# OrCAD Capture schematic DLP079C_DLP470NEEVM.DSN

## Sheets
1 PAGE-07 Revision History
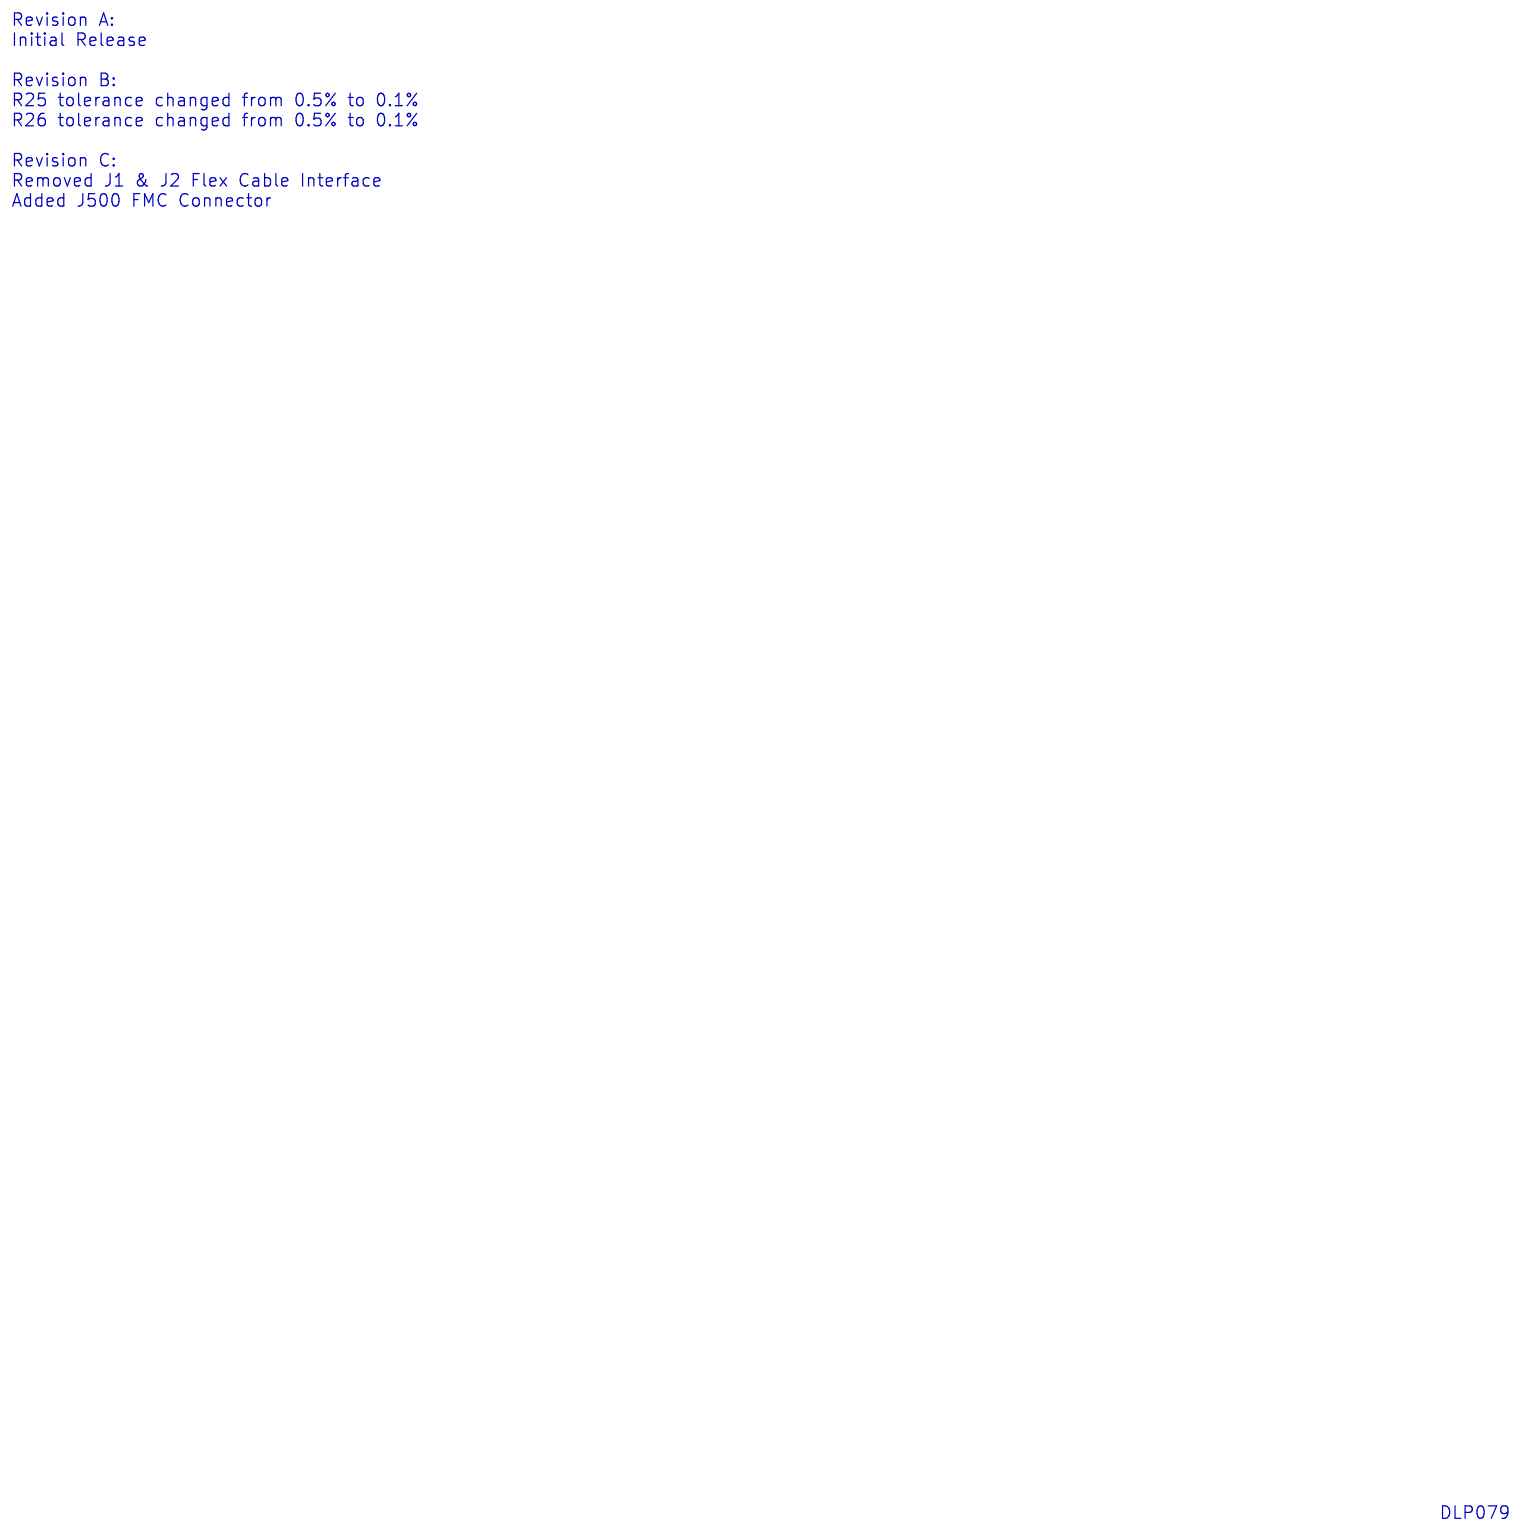
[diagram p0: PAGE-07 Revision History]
2 PAGE-03 Input FMC Connector: size D
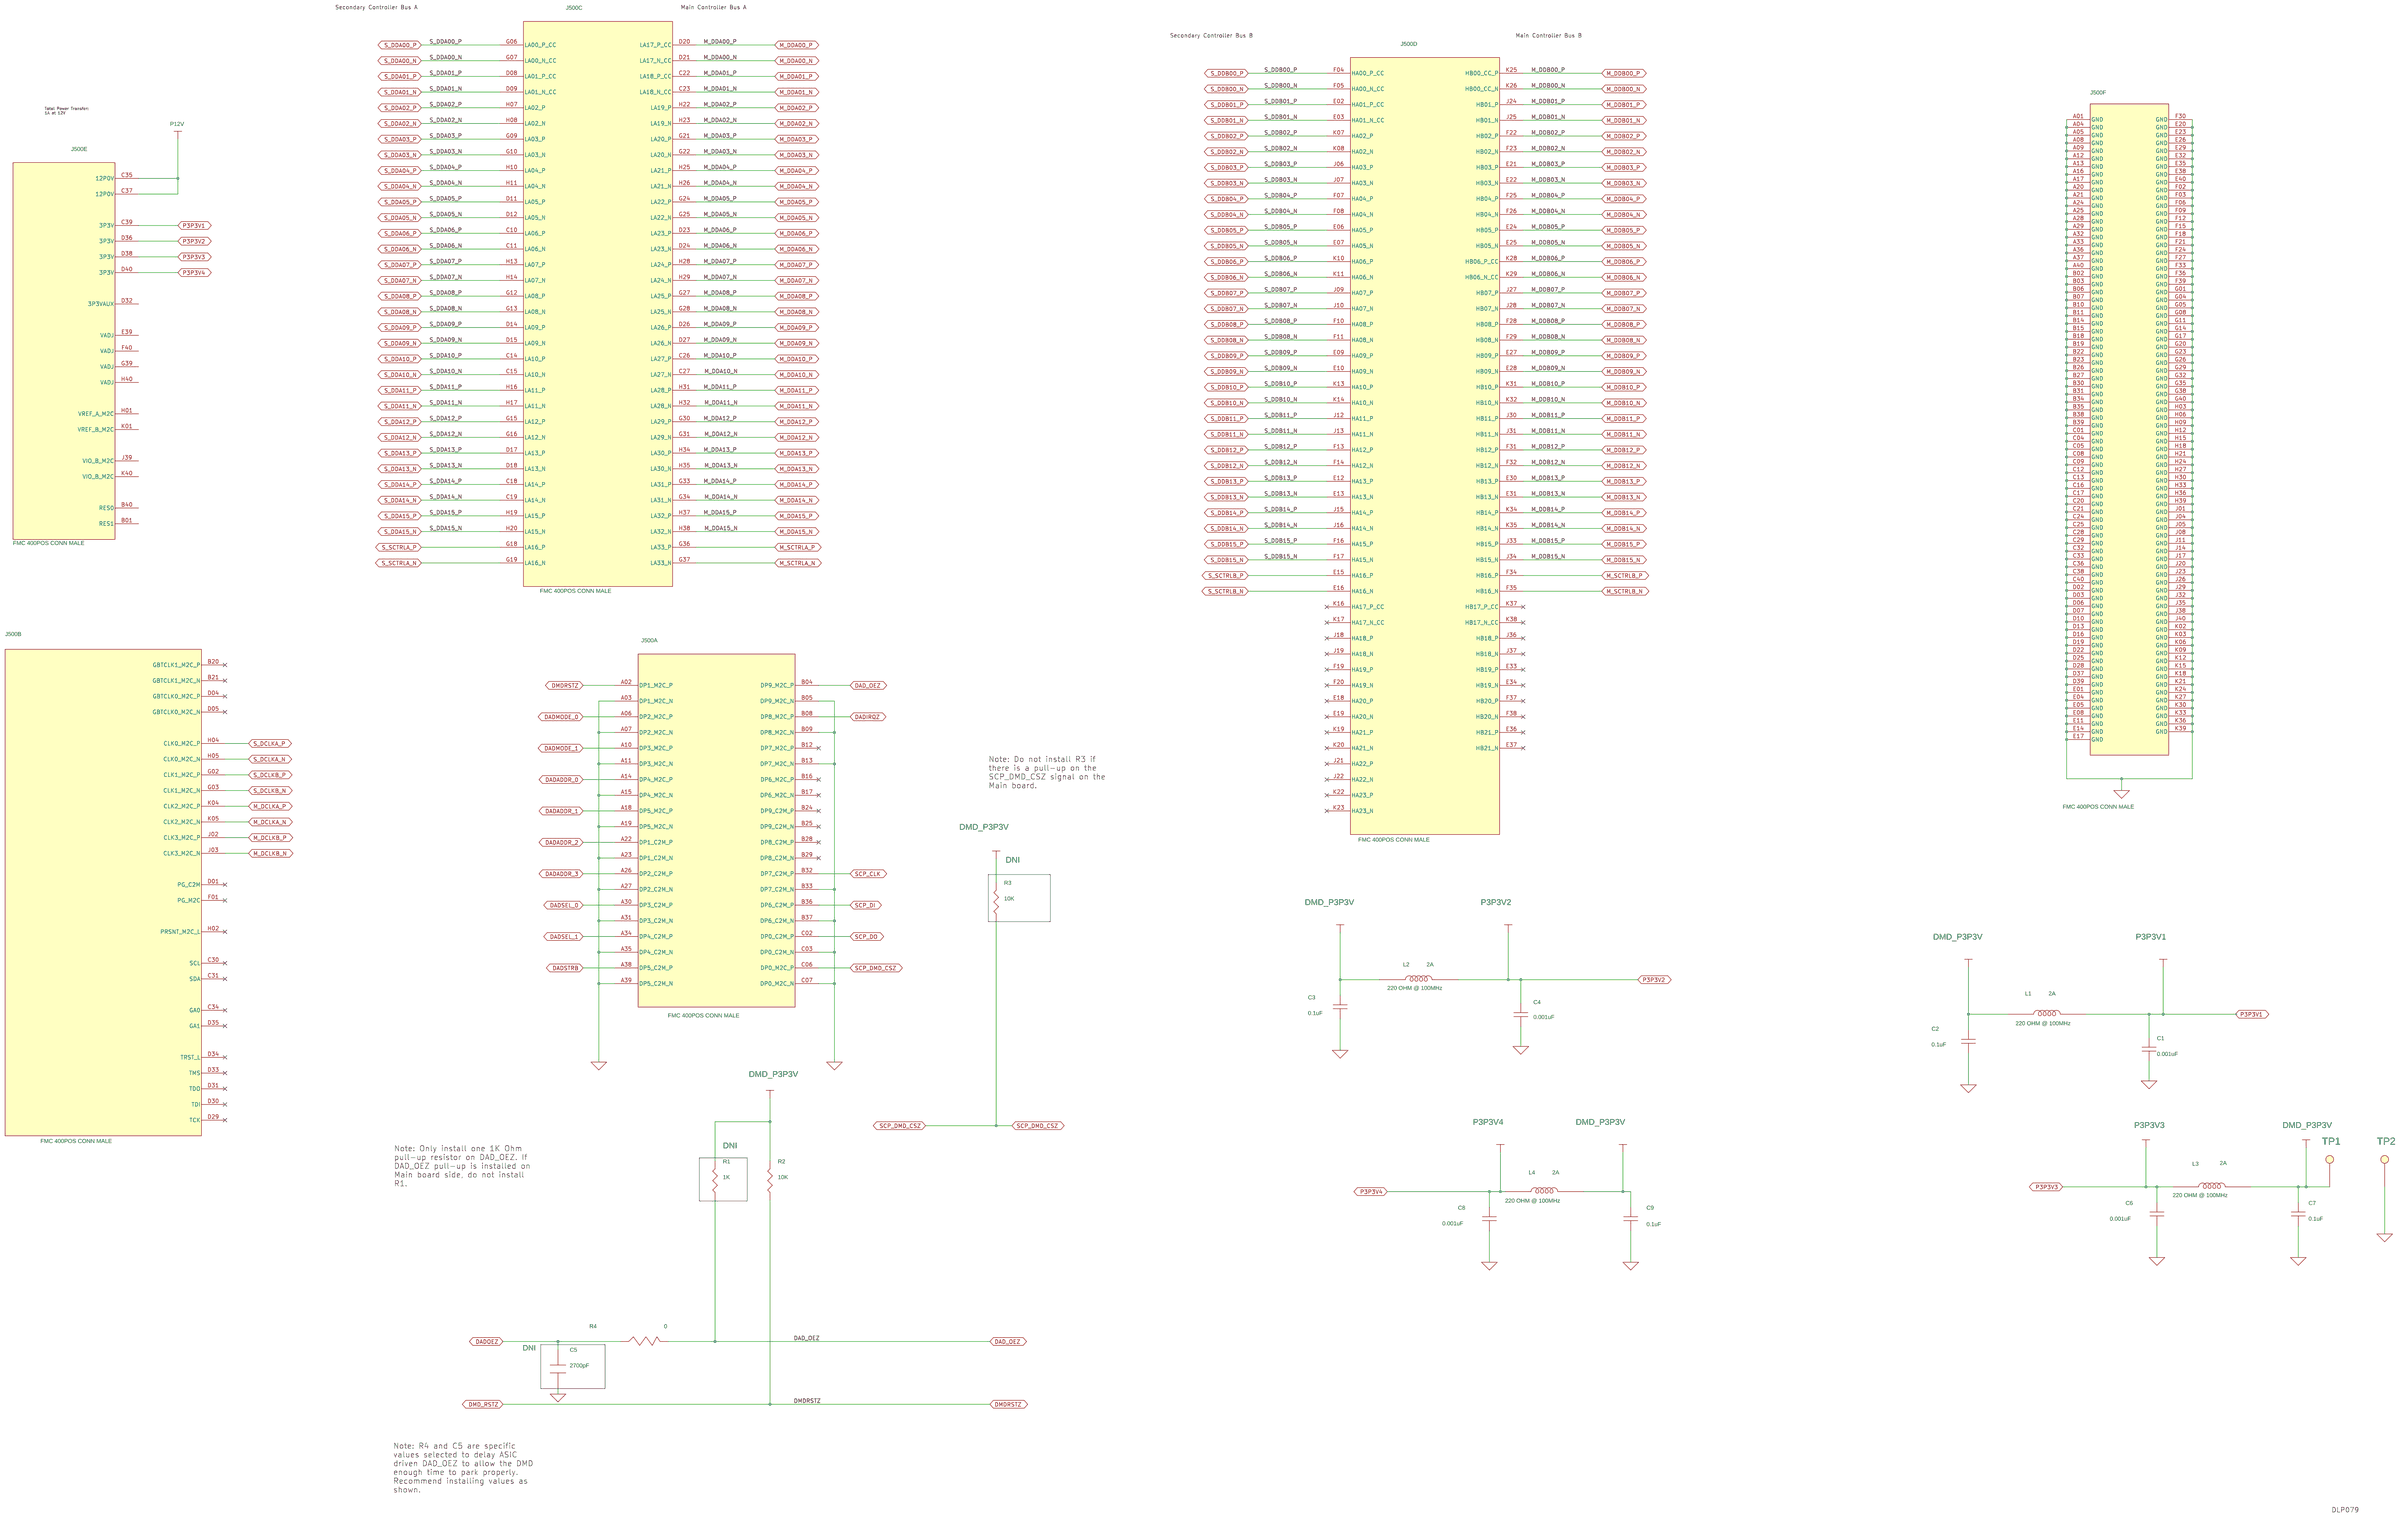
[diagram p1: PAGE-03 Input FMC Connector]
3 PAGE-01 Title Page: rev: D
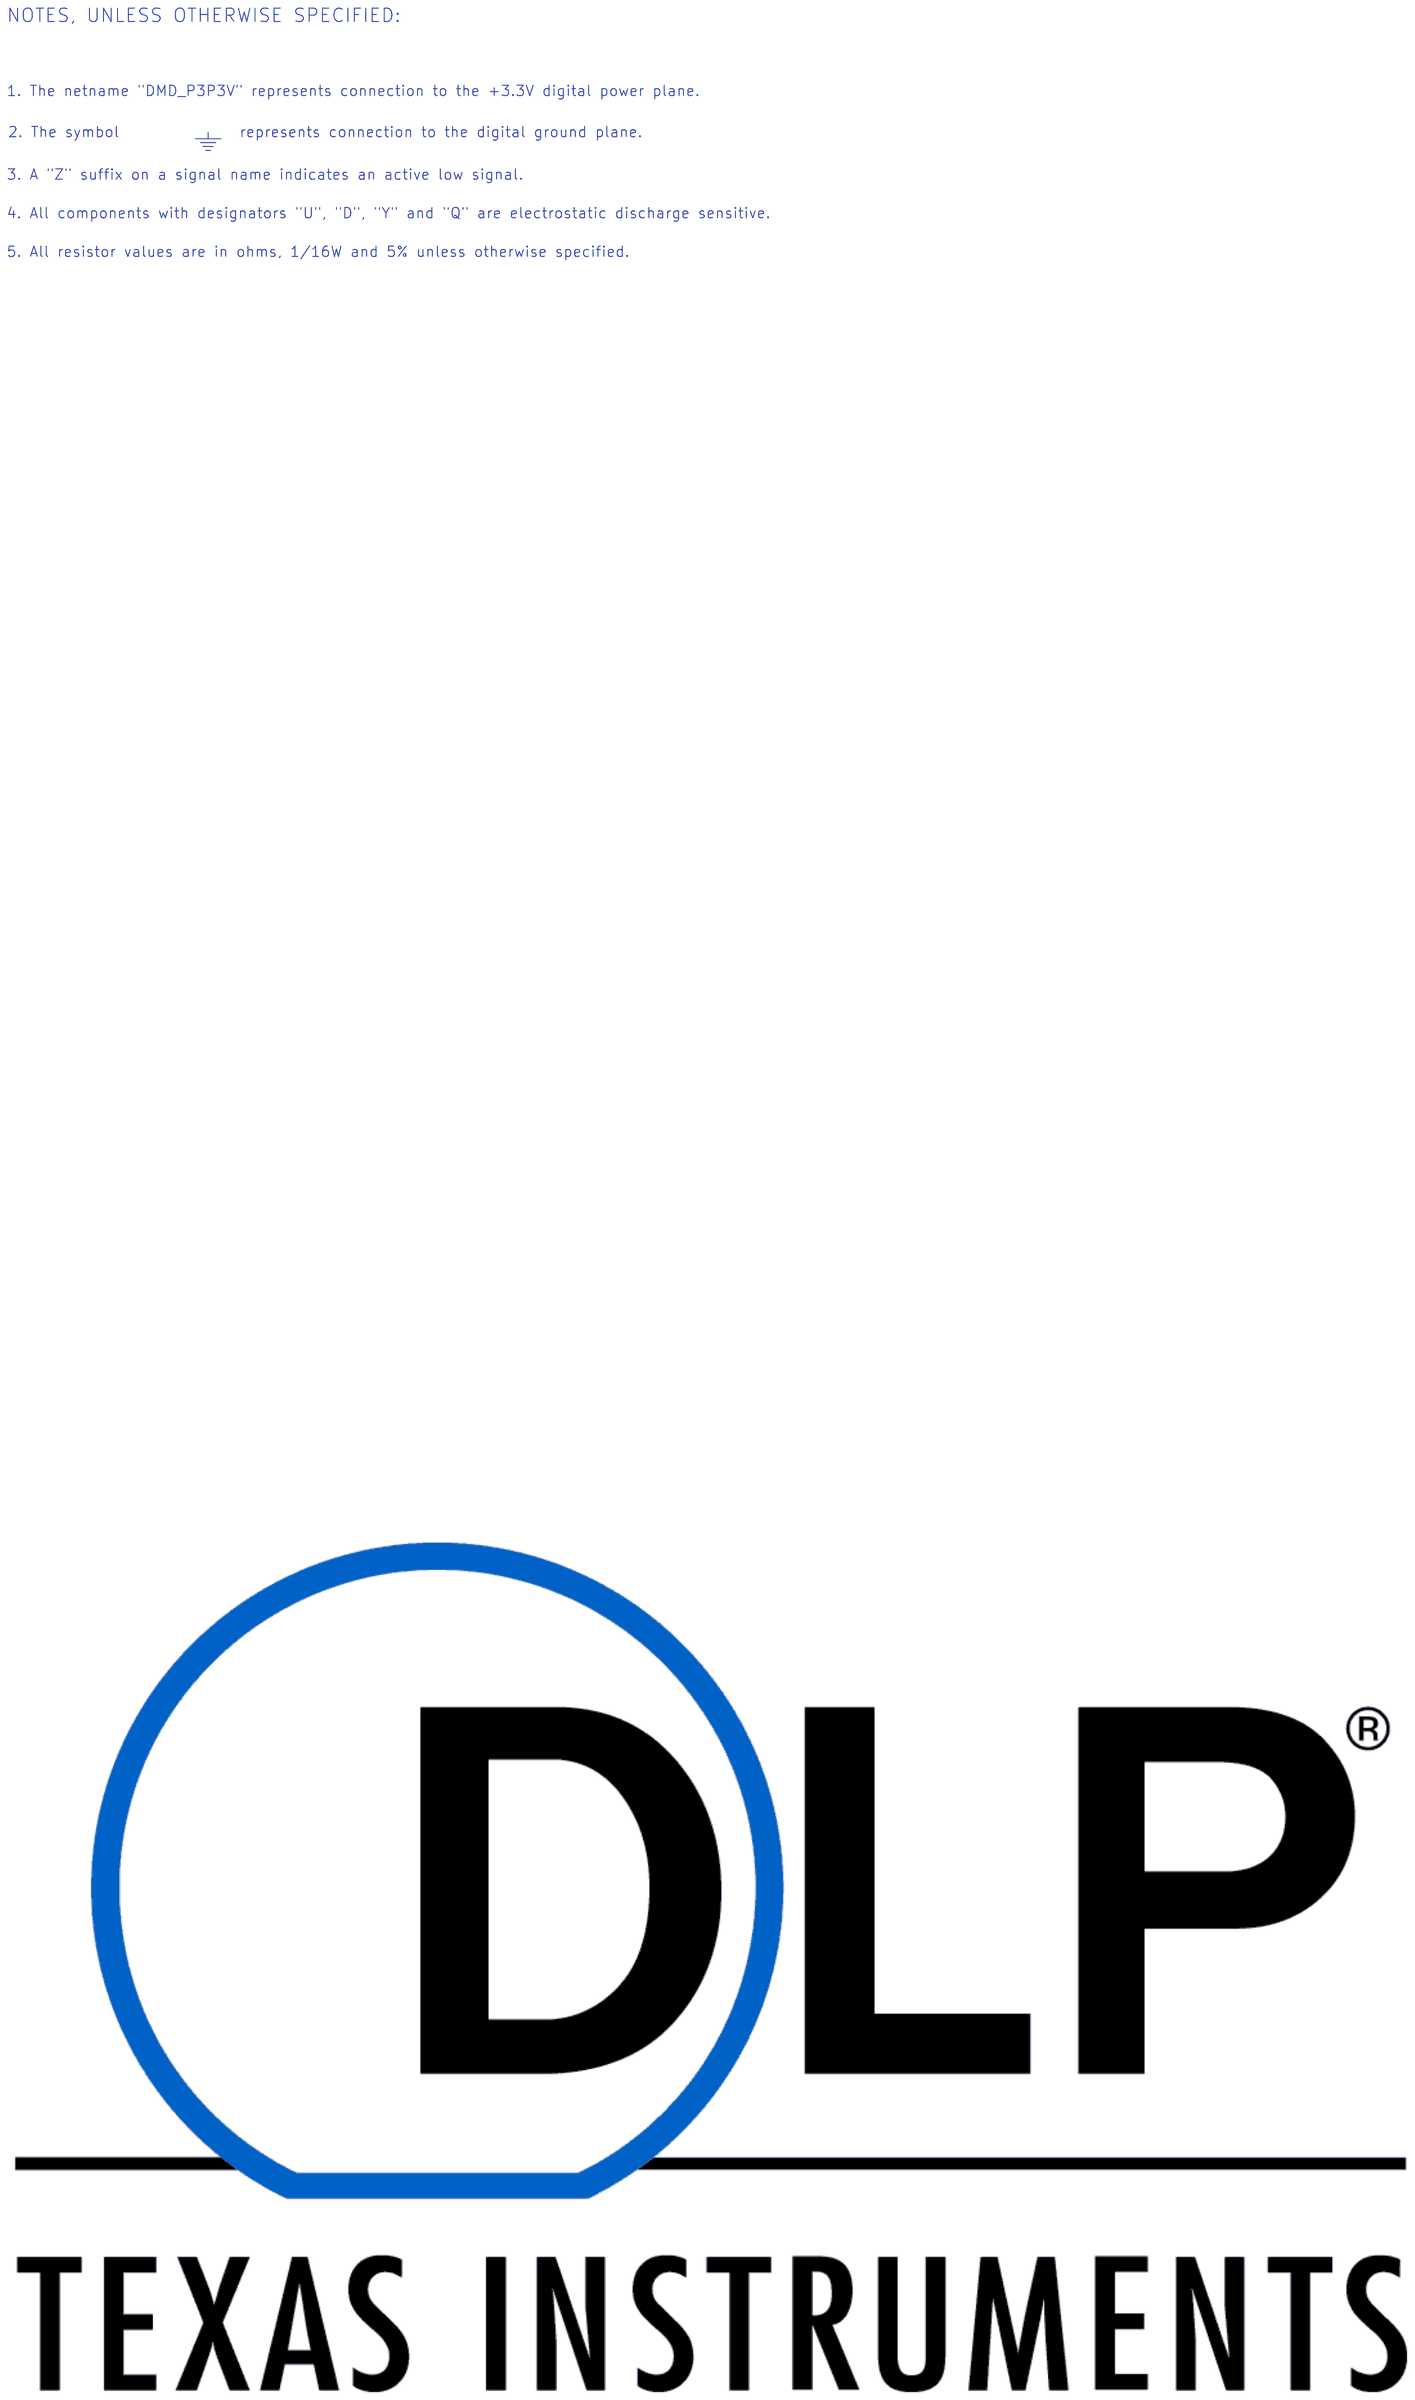
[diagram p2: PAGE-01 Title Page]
4 PAGE-02 Block Diagram
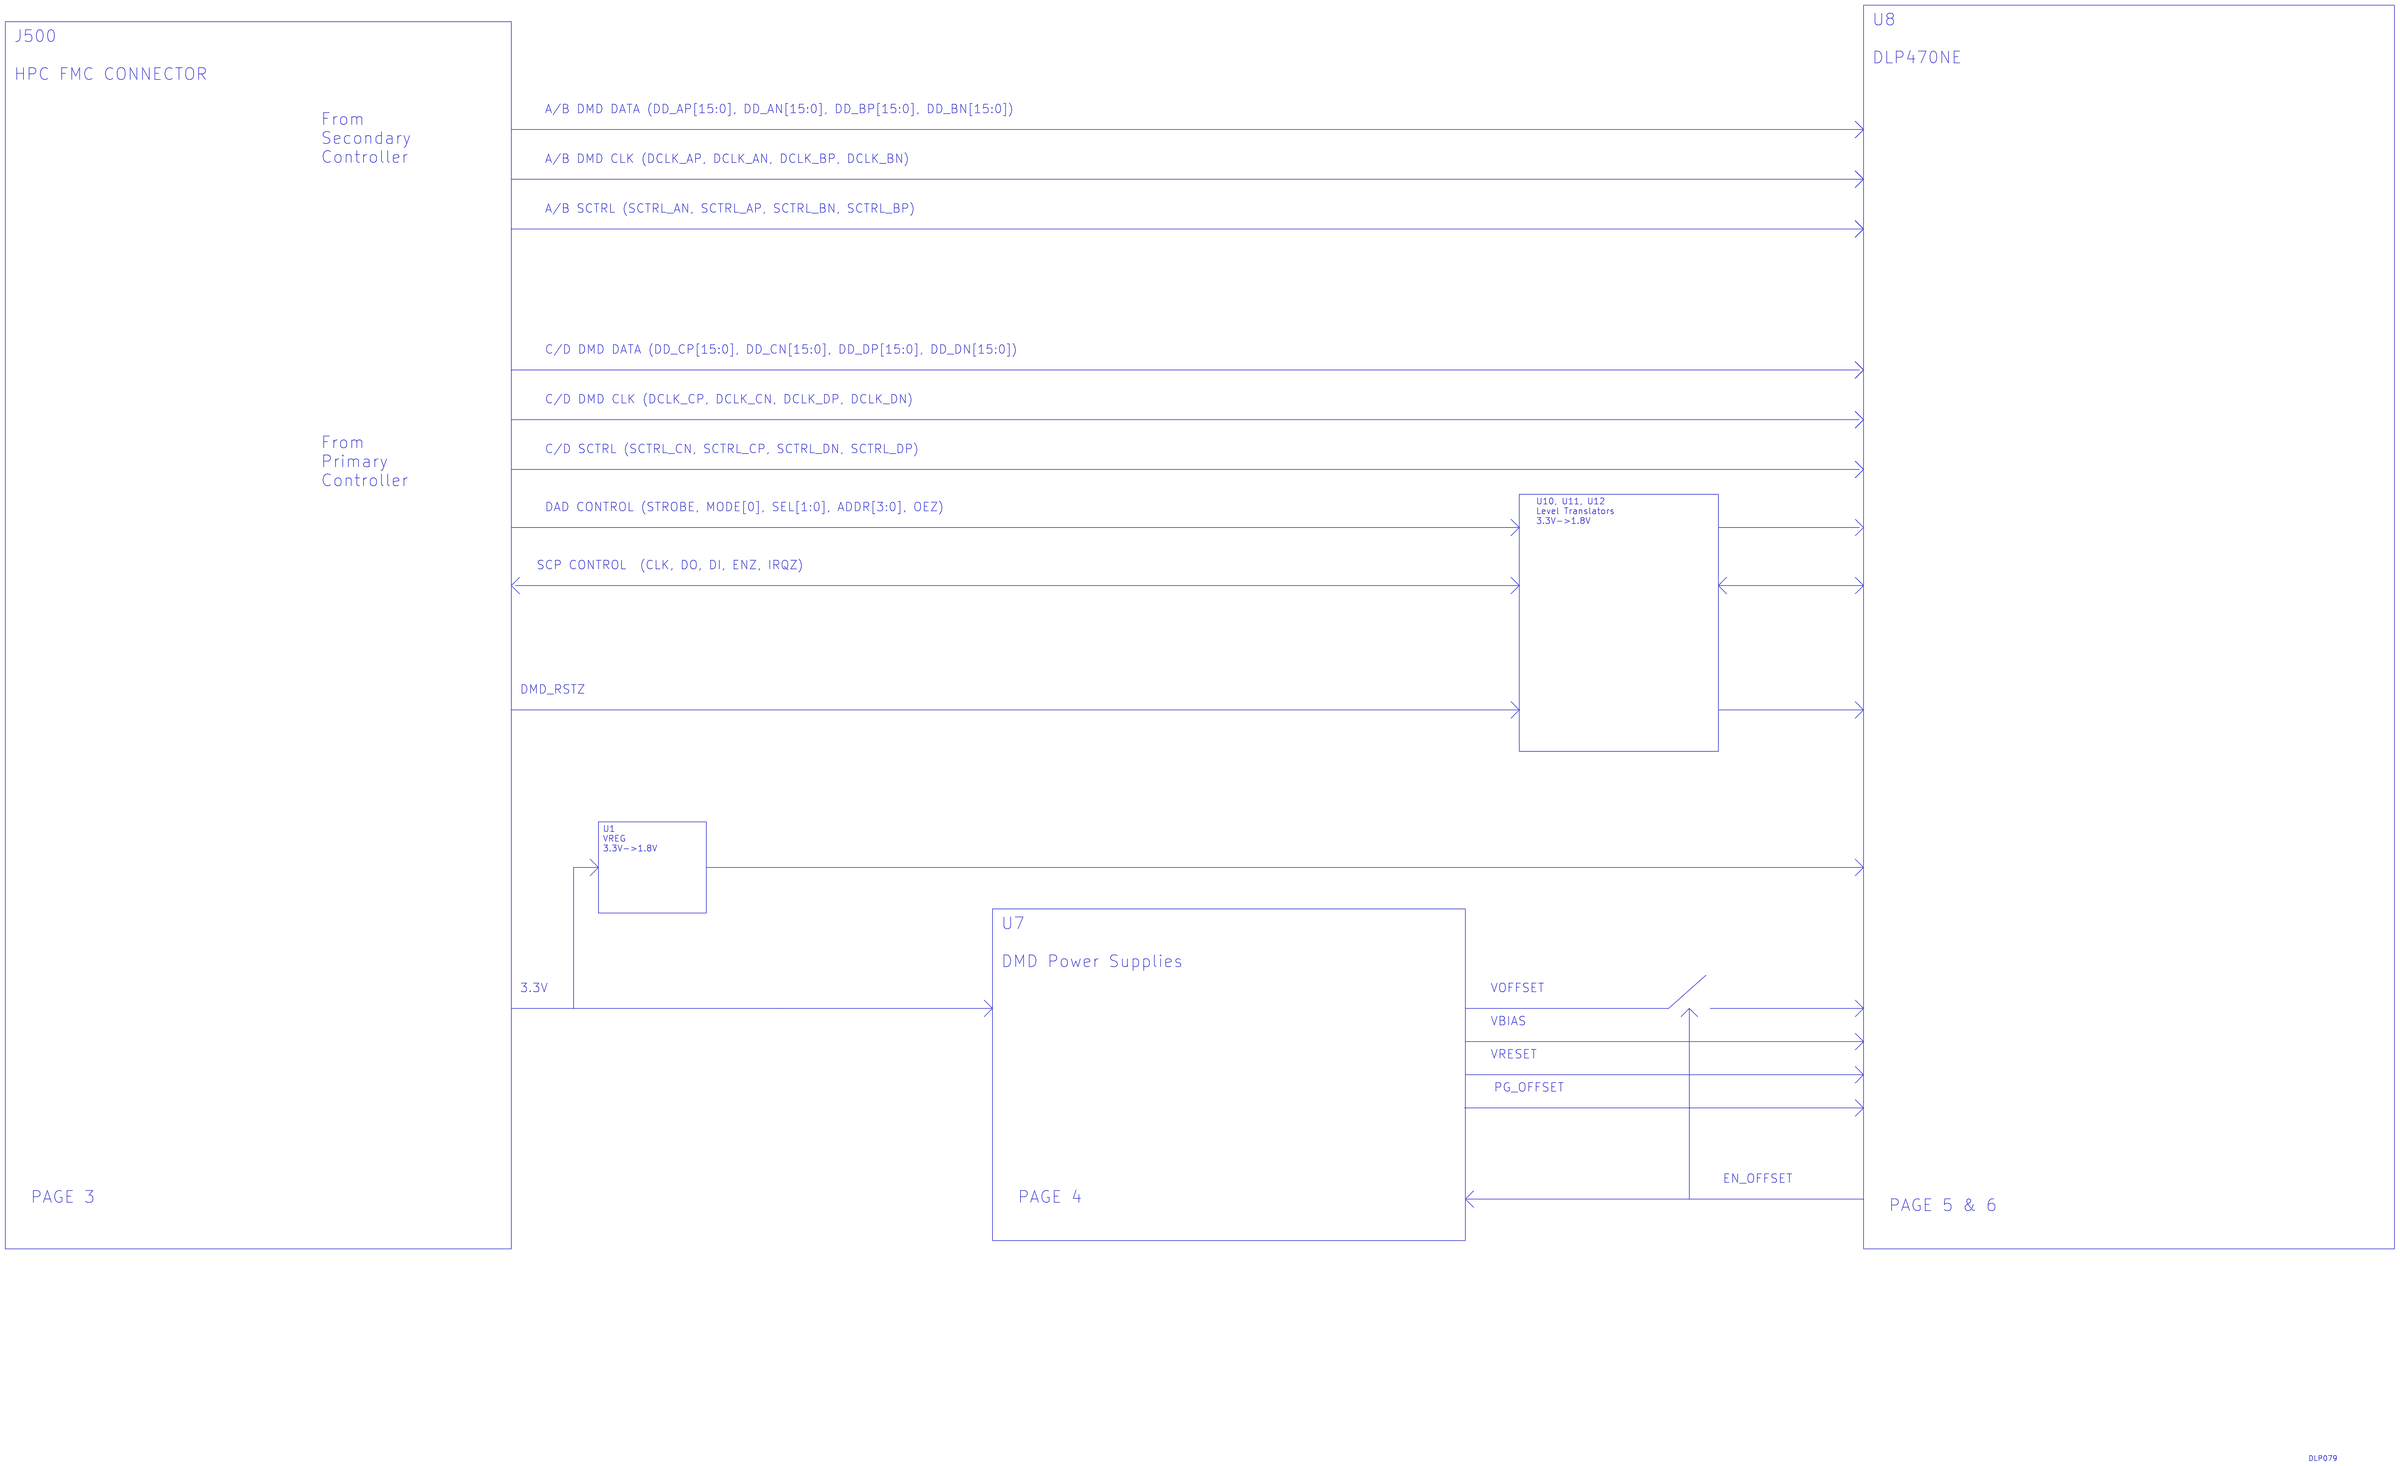
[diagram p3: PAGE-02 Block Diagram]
5 PAGE-04 DMD Pwr Supplies: size D
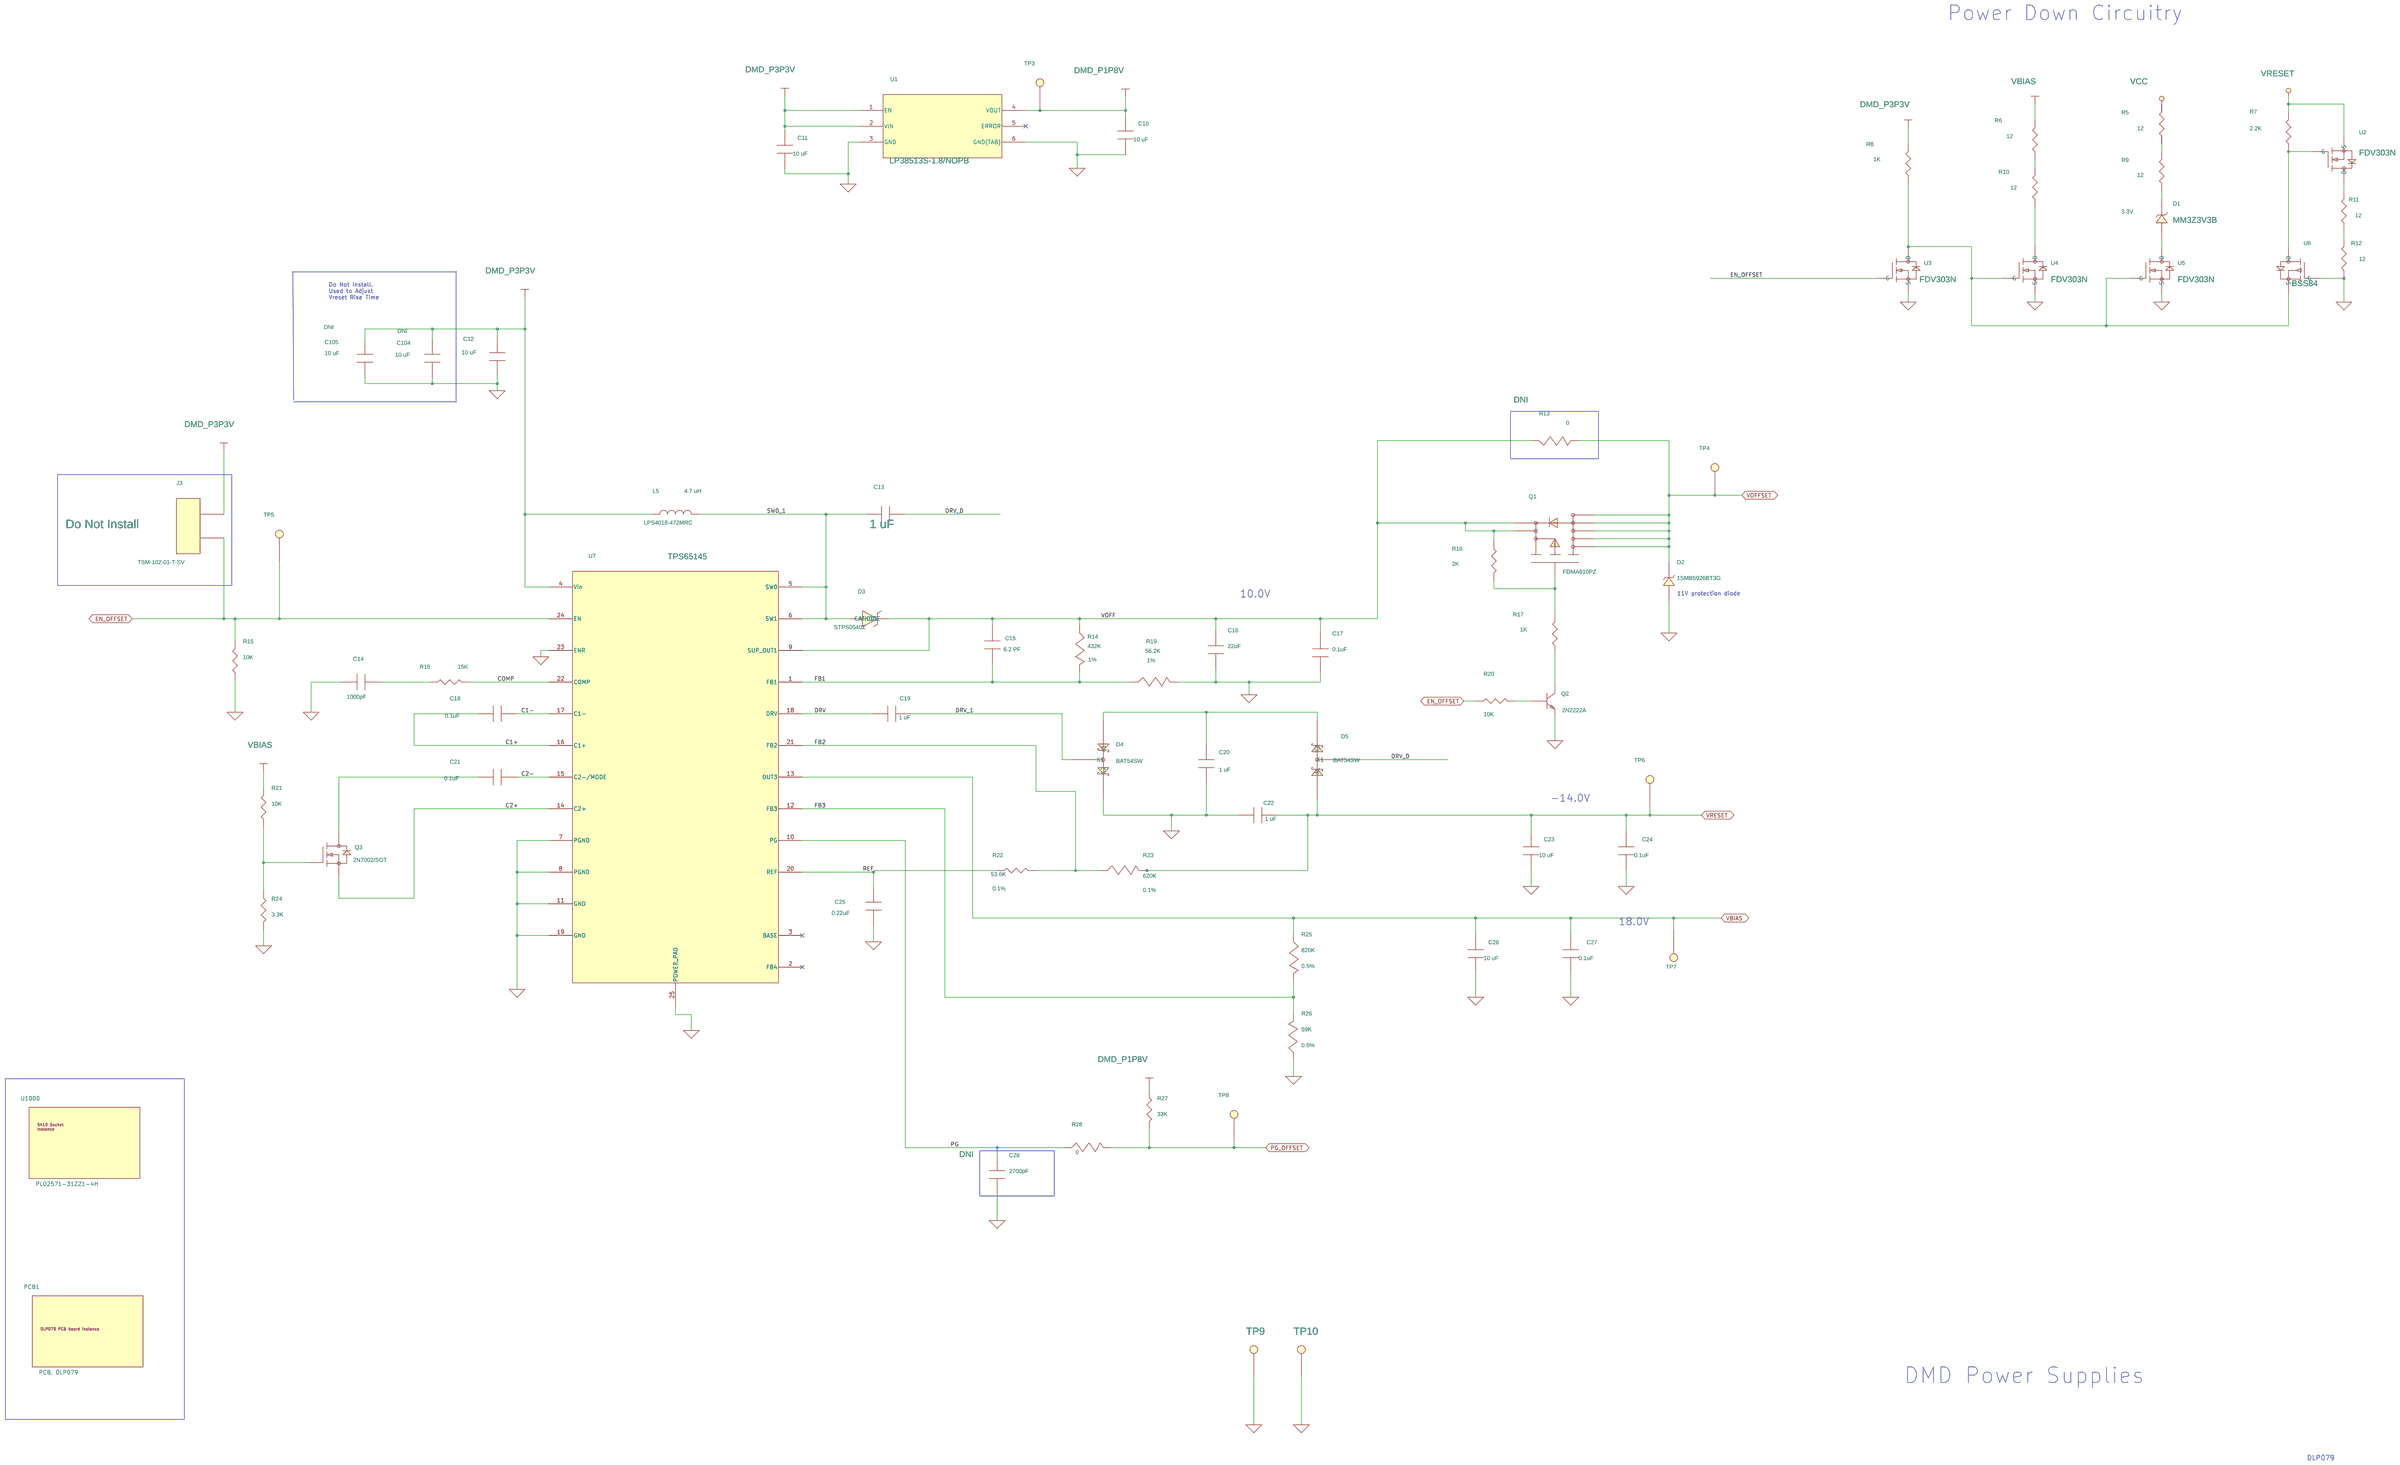
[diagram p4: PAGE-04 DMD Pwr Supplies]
6 PAGE-08 Important Notice
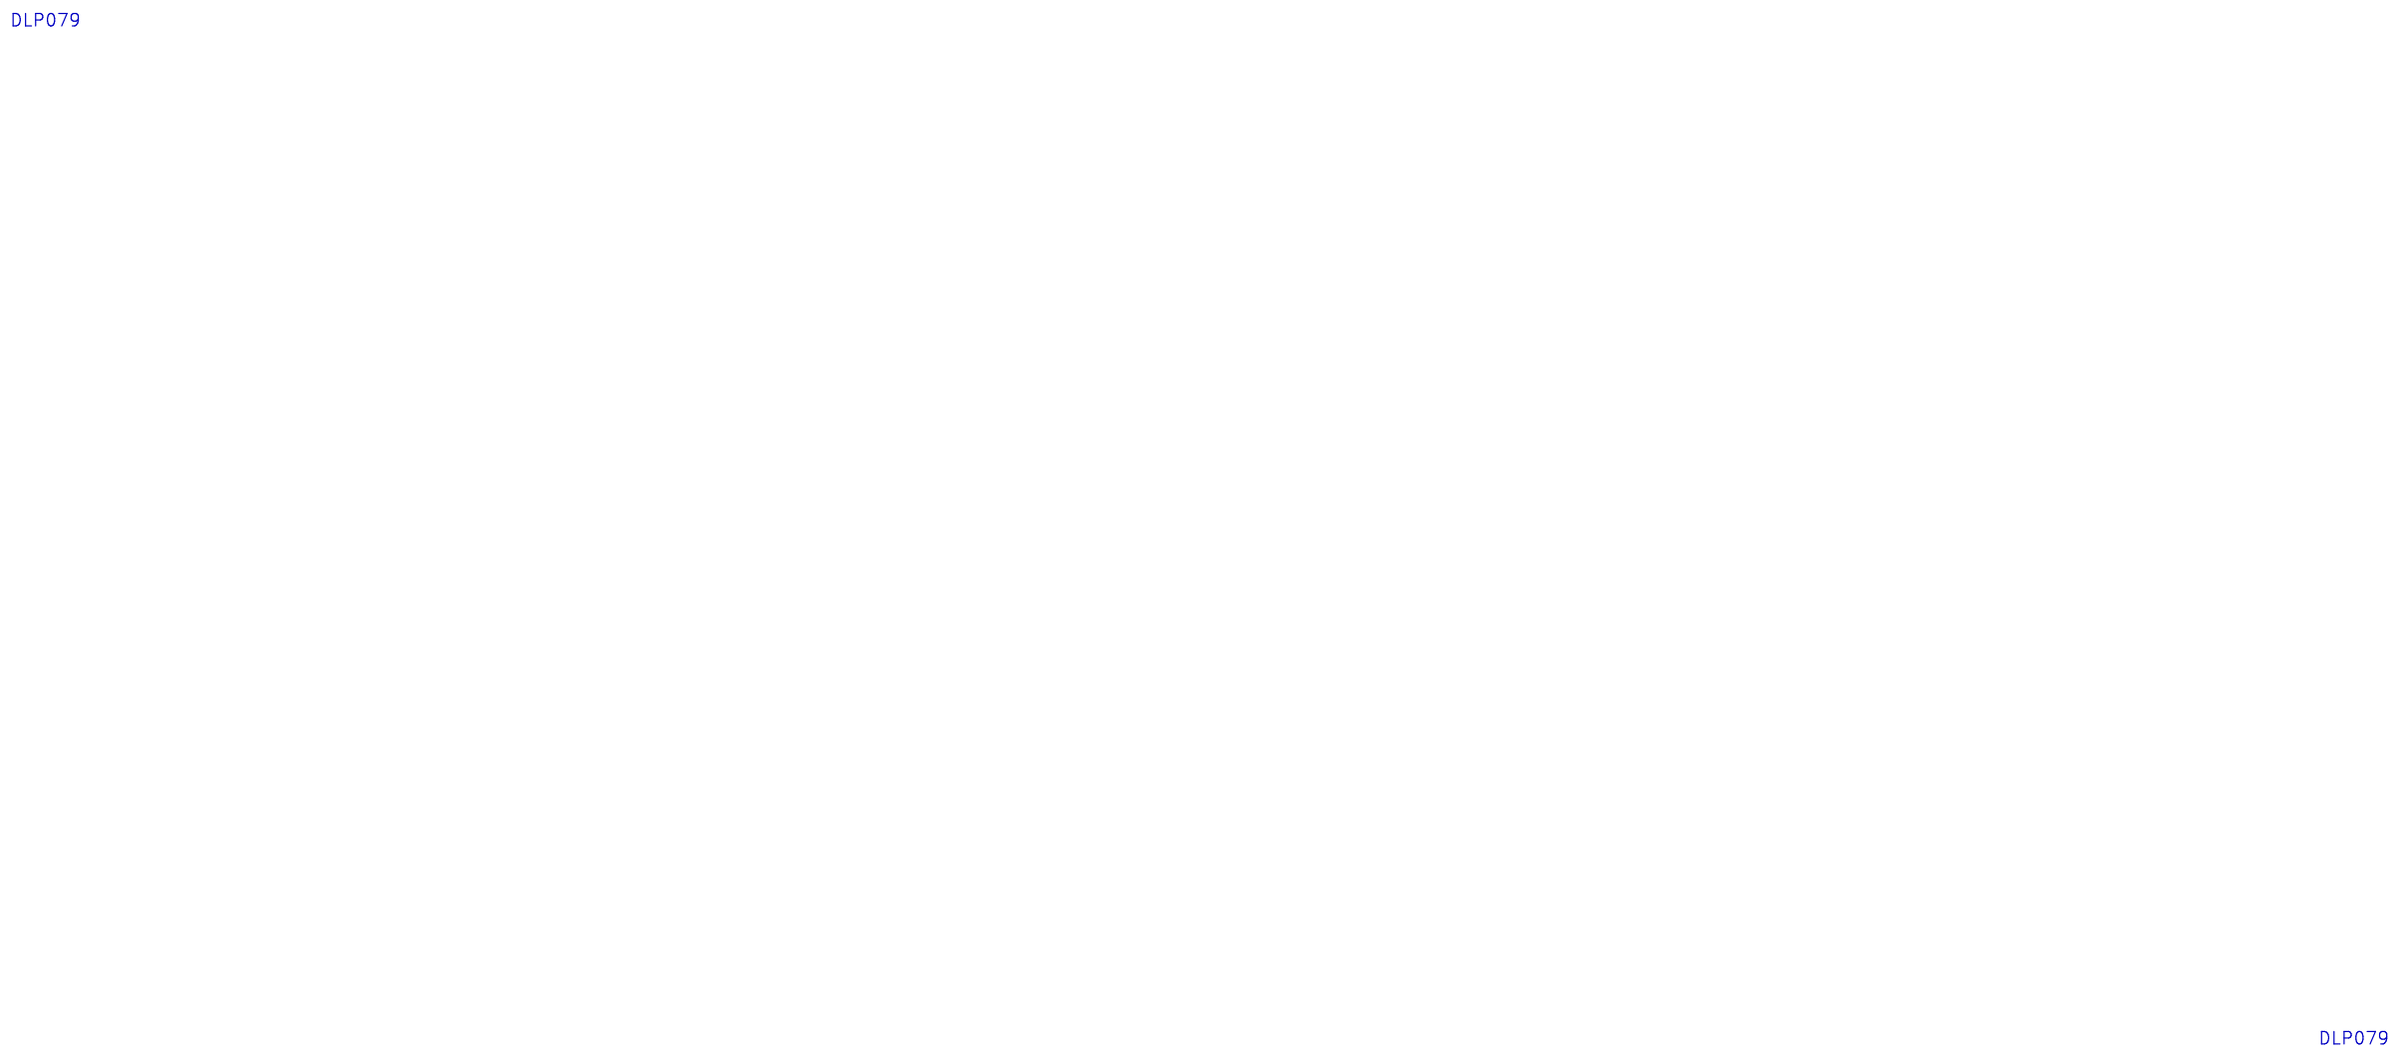
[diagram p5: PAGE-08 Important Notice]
7 PAGE-06 DMD Pwr/Gnd: size D
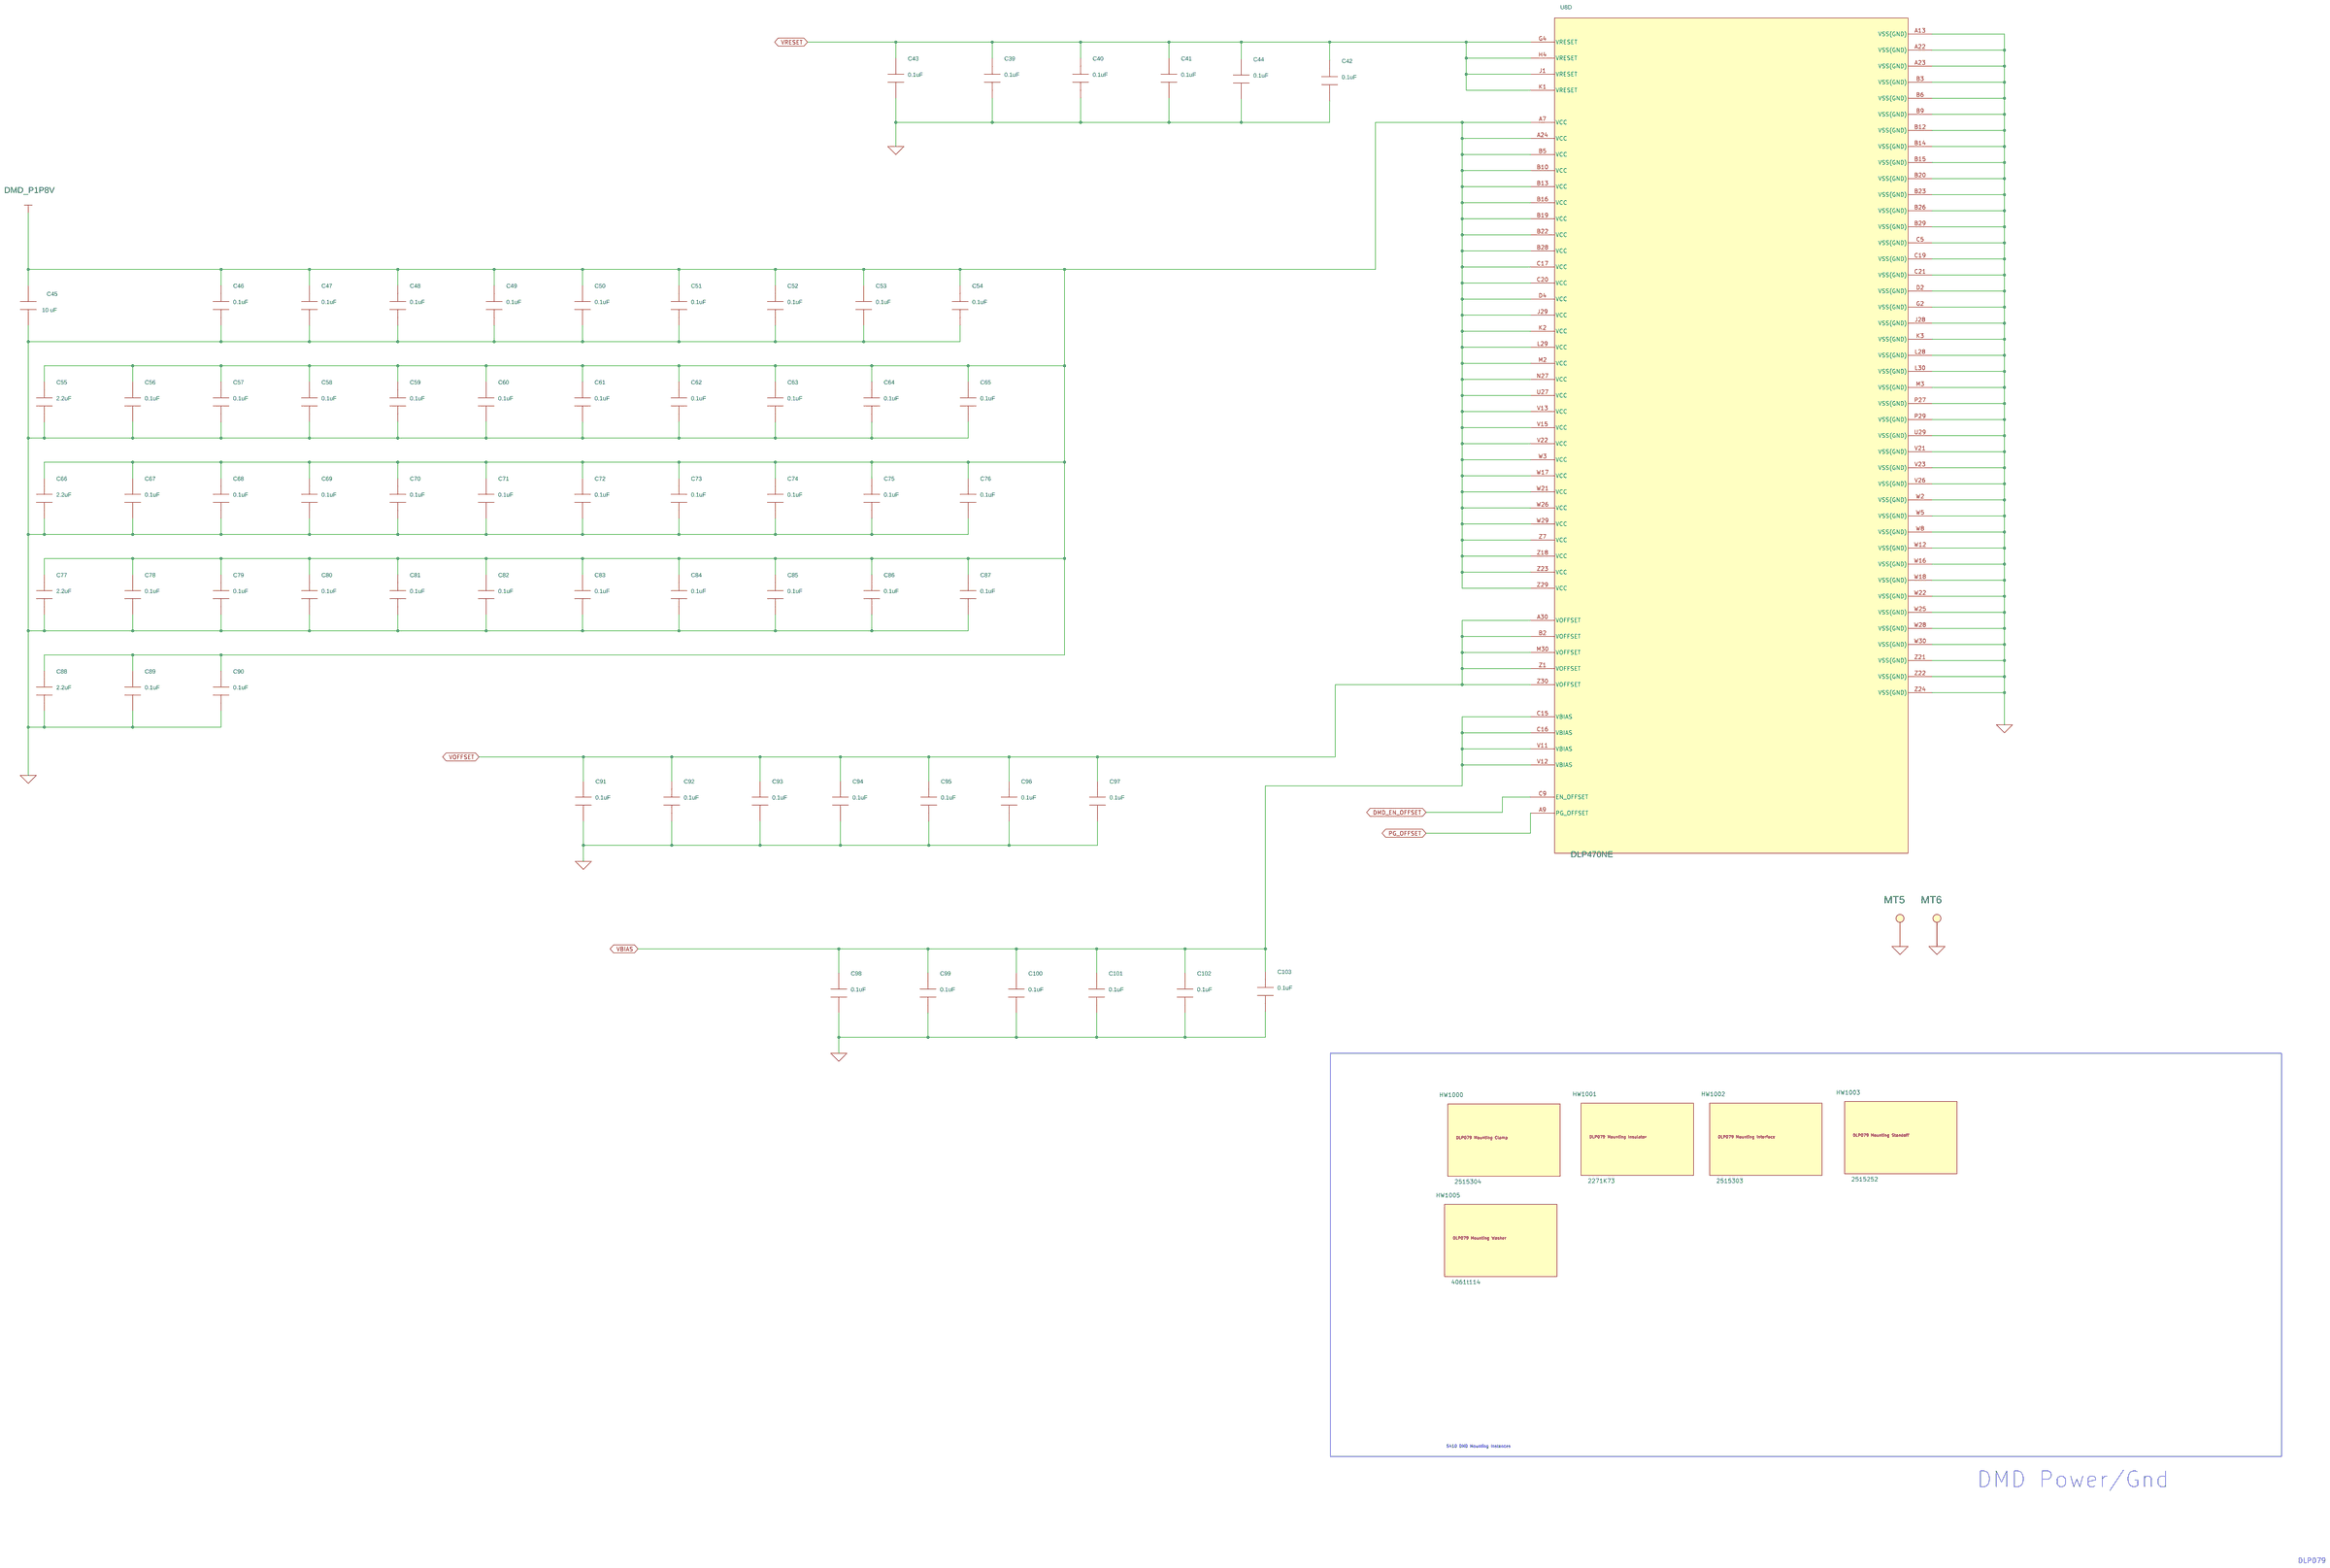
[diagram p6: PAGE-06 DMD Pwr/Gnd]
8 PAGE-05 DMD Data/Control: size D
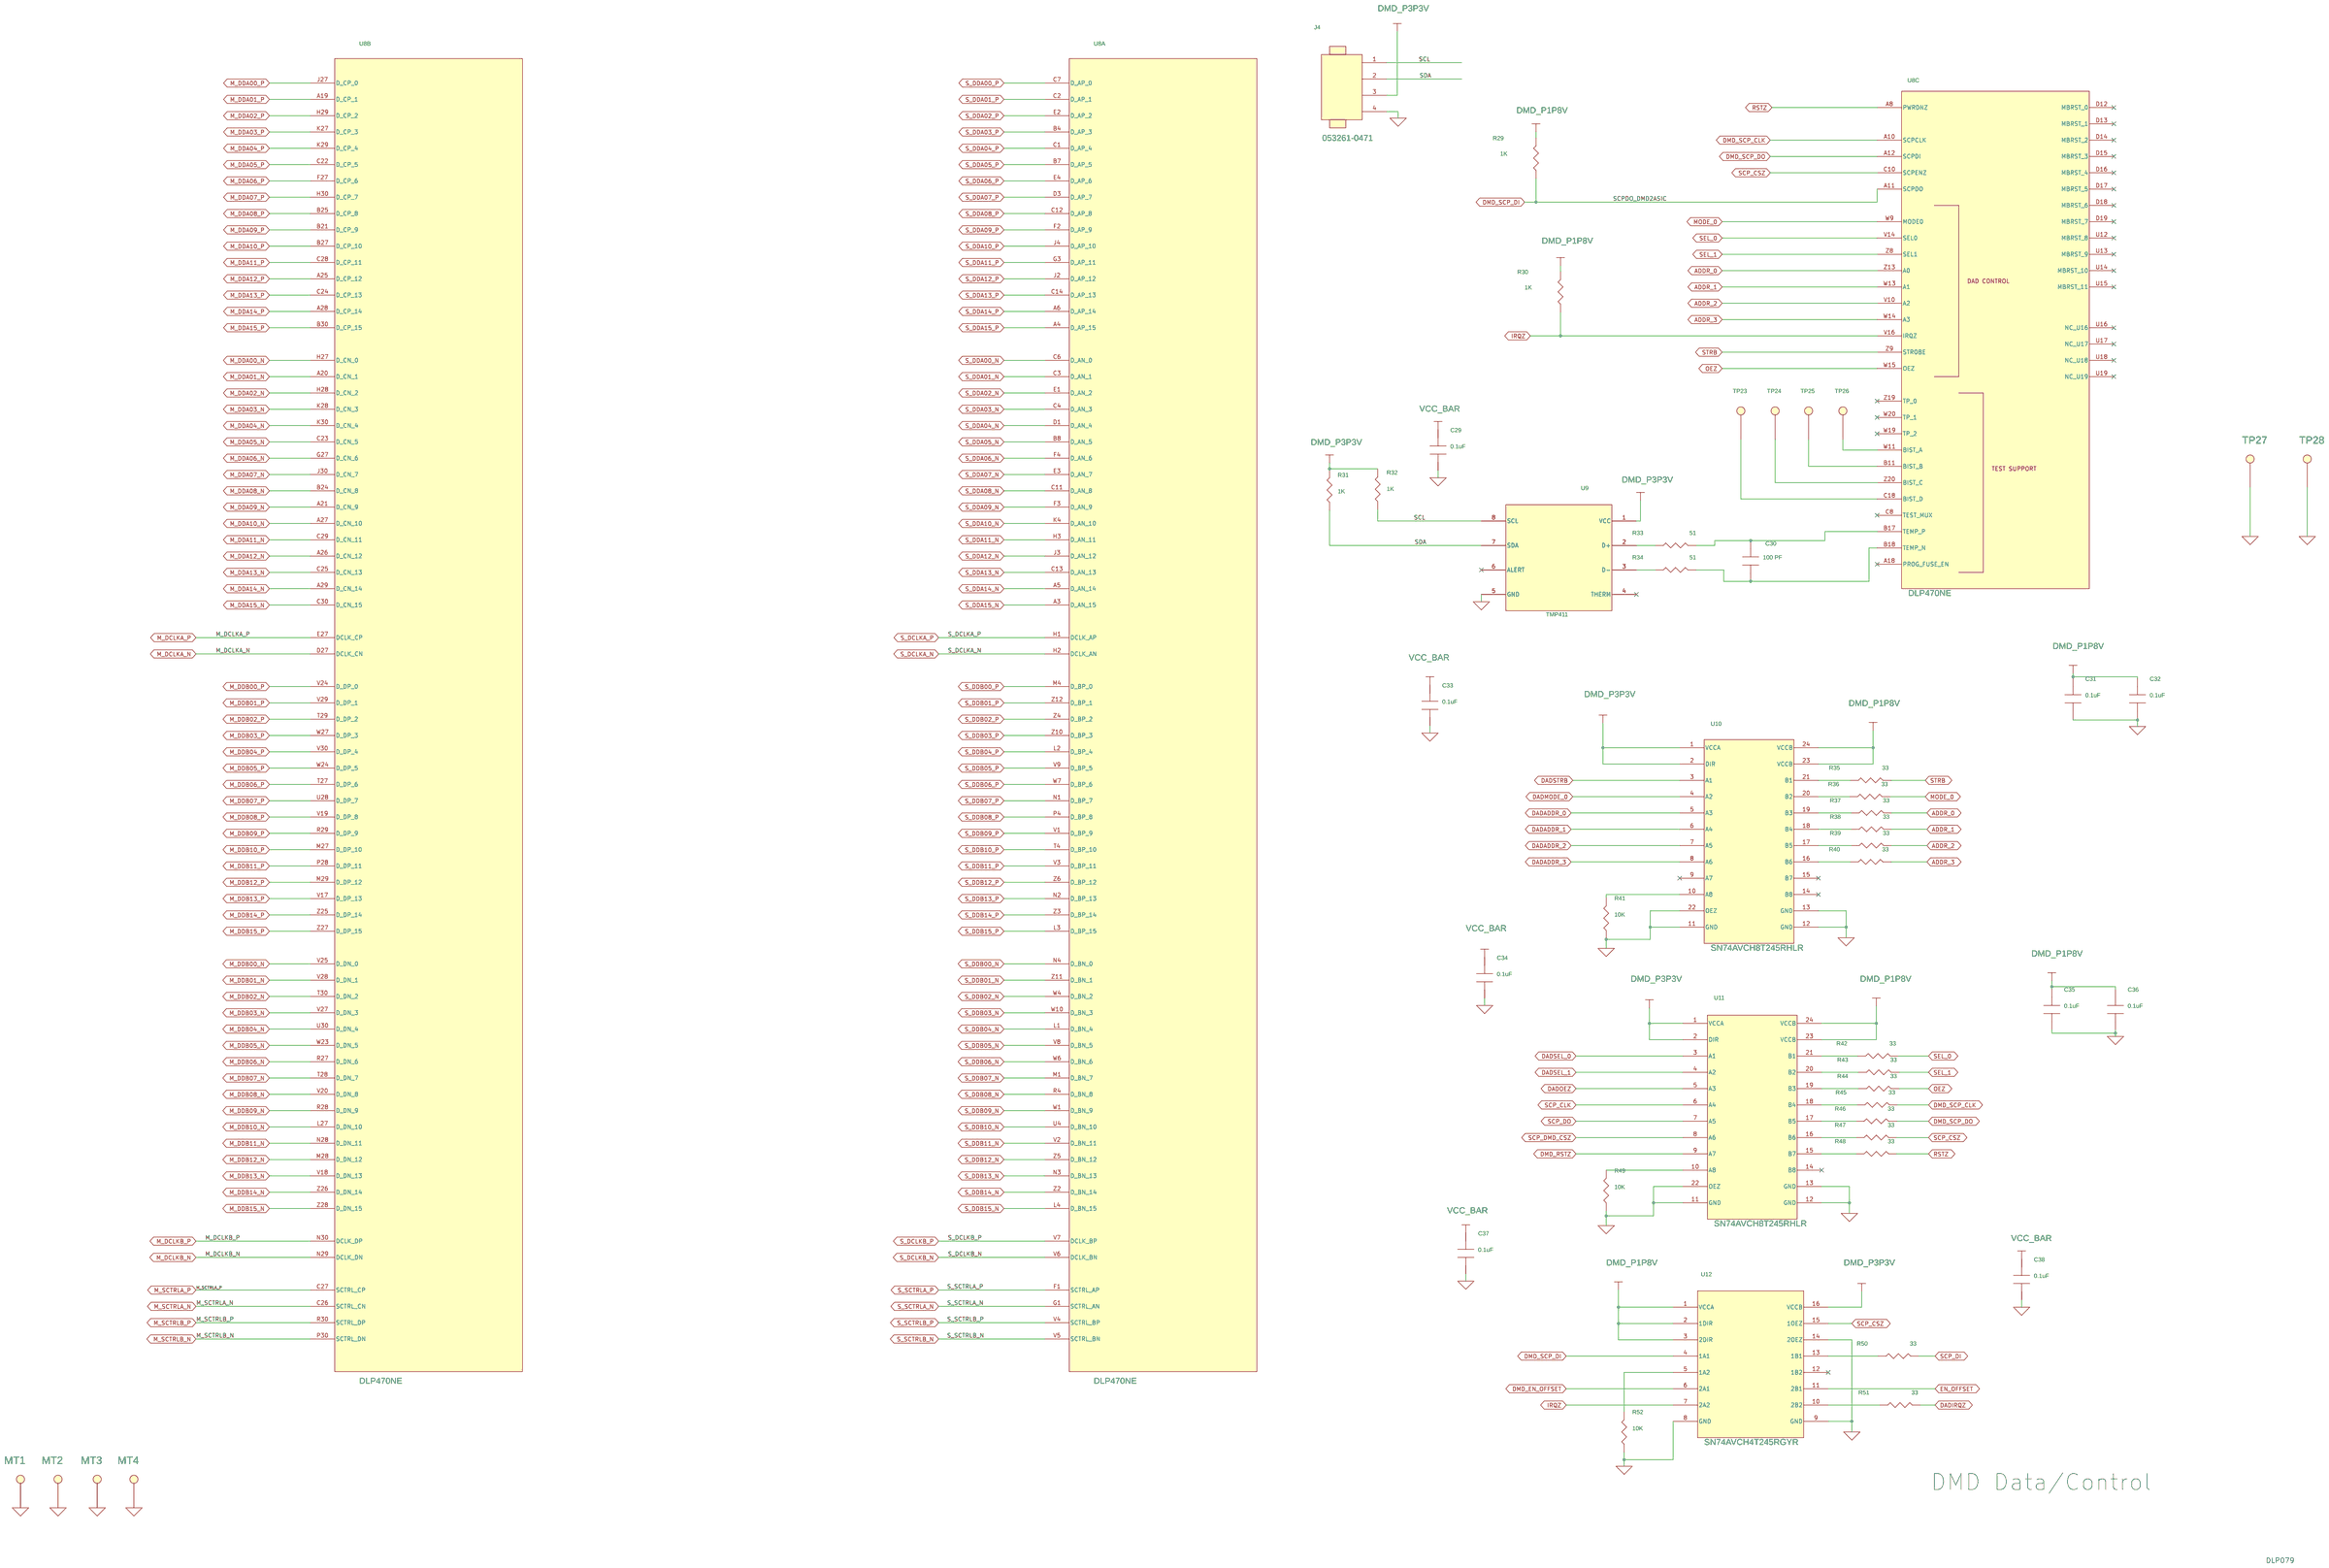
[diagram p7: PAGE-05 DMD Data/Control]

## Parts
sheet PAGE-03 Input FMC Connector
C1  0.001uF  [0603AVX]
C2  0.1uF  [0603AVX]
C3  0.1uF  [0603AVX]
C4  0.001uF  [0603AVX]
C5  2700pF  [0402avx]
C6  0.001uF  [0603AVX]
C7  0.1uF  [0603AVX]
C8  0.001uF  [0603AVX]
C9  0.1uF  [0603AVX]
J500  FMC 400POS CONN MALE  [CONN400-SEAM-40-A-A_SAM-ALPHA]  (sections A,B,C,D,E,F)
L1  220 OHM @ 100MHz  [0805avx]
L2  220 OHM @ 100MHz  [0805avx]
L3  220 OHM @ 100MHz  [0805avx]
L4  220 OHM @ 100MHz  [0805avx]
R1  1K  [0603AVX]
R2  10K  [0603AVX]
R3  10K  [0603AVX]
R4  0  [0603avx]
TP1  Testpoint  [TP40_24]
TP2  Testpoint  [TP40_24]
sheet PAGE-04 DMD Pwr Supplies
C10  10 uF  [1210]
C11  10 uF  [1210]
C12  10 uF  [1210]
C13  1 uF  [0603AVX]
C14  1000pF  [0805avx]
C15  6.2 PF  [0402AVX]
C16  22uF  [1210]
C17  0.1uF  [0805avx]
C18  0.1uF  [0805avx]
C19  1 uF  [0603AVX]
C20  1 uF  [0603AVX]
C21  0.1uF  [0805avx]
C22  1 uF  [0603AVX]
C23  10 uF  [1210]
C24  0.1uF  [0805avx]
C25  0.22uF  [0805AVX]
C26  10 uF  [1210]
C27  0.1uF  [0805avx]
C28  2700pF  [0402avx]
C104  10 uF  [1210]
C105  10 uF  [1210]
D1  3.3V  [SC-90A]
D2  11V  [DO214AA]
D3  STPS0540Z  [SOD123]
D4  BAT54SW  [sot323avx]
D5  BAT54SW  [sot323avx]
J3  TSM-102-01-T-SV  [CONN_2POS_2p54MM]
L5  4.7 uH  [IND_LPS4018]
PCB1  PCB, DLP079
Q1  FDMA910PZ  [MicroFET_2x2]
Q2  2N2222A  [SOT-23-3]
Q3  2N7002/SOT  [SOT-23]
R5  12  [0805]
R6  12  [0805]
R7  2.2K  [0402]
R8  1K  [0402]
R9  12  [0805]
R10  12  [0805]
R11  12  [0805]
R12  12  [0805]
R13  0  [0603avx]
R14  432K  [0603avx]
R15  10K  [0603AVX]
R16  2K  [RES_0402]
R17  1K  [0402]
R18  15K  [0603AVX]
R19  56.2K  [0603avx]
R20  10K  [0402]
R21  10K  [0603AVX]
R22  53.6K  [0603avx]
R23  620K  [0603avx]
R24  3.3K  [0402]
R25  820K  [RES0805]
R26  59K  [0603avx]
R27  33K  [0402]
R28  0  [0603avx]
TP3  Testpoint  [TP40_24_TH]
TP4  Testpoint  [TP40_24_TH]
TP5  Testpoint  [TP40_24]
TP6  Testpoint  [TP40_24_TH]
TP7  Testpoint  [TP40_24_TH]
TP8  Testpoint  [TP40_24]
TP9  Testpoint  [TP40_24]
TP10  Testpoint  [TP40_24]
U1  LP38513S-1.8/NOPB  [TO-263]
U2  N-CHANNEL MOSFET  [SOT23AVX]
U3  N-CHANNEL MOSFET  [SOT23AVX]
U4  N-CHANNEL MOSFET  [SOT23AVX]
U5  N-CHANNEL MOSFET  [SOT23AVX]
U6  BSS84  [SOT23AVX]
U7  TPS65145  [SOIC24-PWP_TI]
U1000  PL02571-31ZZ1-4H  [S410]
sheet PAGE-05 DMD Data/Control
C29  0.1uF  [0603avx]
C30  100 PF  [0402AVX]
C31  0.1uF  [0603avx]
C32  0.1uF  [0603avx]
C33  0.1uF  [0603avx]
C34  0.1uF  [0603avx]
C35  0.1uF  [0603avx]
C36  0.1uF  [0603avx]
C37  0.1uF  [0603avx]
C38  0.1uF  [0603avx]
J4  Conn_4  [CONN_4]
MT1  MT2  [MT2]
MT2  MT2  [MT2]
MT3  MT2  [MT2]
MT4  MT2  [MT2]
R29  1K  [0402]
R30  1K  [0402]
R31  1K  [0603AVX]
R32  1K  [0603AVX]
R33  51  [0402AVX]
R34  51  [0402AVX]
R35  33  [0402AVX]
R36  33  [0402AVX]
R37  33  [0402AVX]
R38  33  [0402AVX]
R39  33  [0402AVX]
R40  33  [0402AVX]
R41  10K  [0603AVX]
R42  33  [0402AVX]
R43  33  [0402AVX]
R44  33  [0402AVX]
R45  33  [0402AVX]
R46  33  [0402AVX]
R47  33  [0402AVX]
R48  33  [0402AVX]
R49  10K  [0603AVX]
R50  33  [0402AVX]
R51  33  [0402AVX]
R52  10K  [0603AVX]
TP23  Testpoint  [TP40_24]
TP24  Testpoint  [TP40_24]
TP25  Testpoint  [TP40_24]
TP26  Testpoint  [TP40_24]
TP27  Testpoint  [TP40_24_TH]
TP28  Testpoint  [TP40_24]
U8  DLP470NE  [DMD]  (sections A,B,C,D)
U9  TMP411  [MSOP-8]
U10  SN74AVCH8T245RHLR  [QFN-24]
U11  SN74AVCH8T245RHLR  [QFN-24]
U12  SN74AVCH4T245RGYR  [VQFN]
sheet PAGE-06 DMD Pwr/Gnd
C39  0.1uF  [0603avx]
C40  0.1uF  [0603avx]
C41  0.1uF  [0603avx]
C42  0.1uF  [0603avx]
C43  0.1uF  [0603avx]
C44  0.1uF  [0603avx]
C45  10 uF  [1210]
C46  0.1uF  [0603avx]
C47  0.1uF  [0603avx]
C48  0.1uF  [0603avx]
C49  0.1uF  [0603avx]
C50  0.1uF  [0603avx]
C51  0.1uF  [0603avx]
C52  0.1uF  [0603avx]
C53  0.1uF  [0603avx]
C54  0.1uF  [0603avx]
C55  2.2uF  [0603avx]
C56  0.1uF  [0603avx]
C57  0.1uF  [0603avx]
C58  0.1uF  [0603avx]
C59  0.1uF  [0603avx]
C60  0.1uF  [0603avx]
C61  0.1uF  [0603avx]
C62  0.1uF  [0603avx]
C63  0.1uF  [0603avx]
C64  0.1uF  [0603avx]
C65  0.1uF  [0603avx]
C66  2.2uF  [0603avx]
C67  0.1uF  [0603avx]
C68  0.1uF  [0603avx]
C69  0.1uF  [0603avx]
C70  0.1uF  [0603avx]
C71  0.1uF  [0603avx]
C72  0.1uF  [0603avx]
C73  0.1uF  [0603avx]
C74  0.1uF  [0603avx]
C75  0.1uF  [0603avx]
C76  0.1uF  [0603avx]
C77  2.2uF  [0603avx]
C78  0.1uF  [0603avx]
C79  0.1uF  [0603avx]
C80  0.1uF  [0603avx]
C81  0.1uF  [0603avx]
C82  0.1uF  [0603avx]
C83  0.1uF  [0603avx]
C84  0.1uF  [0603avx]
C85  0.1uF  [0603avx]
C86  0.1uF  [0603avx]
C87  0.1uF  [0603avx]
C88  2.2uF  [0603avx]
C89  0.1uF  [0603avx]
C90  0.1uF  [0603avx]
C91  0.1uF  [0603avx]
C92  0.1uF  [0603avx]
C93  0.1uF  [0603avx]
C94  0.1uF  [0603avx]
C95  0.1uF  [0603avx]
C96  0.1uF  [0603avx]
C97  0.1uF  [0603avx]
C98  0.1uF  [0603avx]
C99  0.1uF  [0603avx]
C100  0.1uF  [0603avx]
C101  0.1uF  [0603avx]
C102  0.1uF  [0603avx]
C103  0.1uF  [0603avx]
HW1000  2515304
HW1001  2271K73
HW1002  2515303
HW1003  2515252
HW1005  4061t114
MT5  MT2  [MT2]
MT6  MT2  [MT2]

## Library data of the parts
C1 C4 C6 C8 = CAP_NP: Capacitor; CCA ITEM: 3; DigiKey Part Number: 478-1215-1-ND; MFG: AVX; Part Number: 06035C102KAT2A; Rating: 50V; Tolerance: 10%; Type: X7R; VOLTAGE: 50V
C2 C3 C7 C9 = CAP_NP: Capacitor; CCA ITEM: 1; DigiKey Part Number: 478-1239-1-ND; MFG: AVX; Part Number: 0603YC104KAT2A; Rating: 16V; Tolerance: 10%; Type: X7R; VOLTAGE: 16V
C5 = CAP_NP_dsize: Capacitor; DNI: DNI; DigiKey Part Number: 311-1033-1-ND; Do Not Install: Do Not Install; ESR: <ESR>; ICA_MFR_NAME: PANASONIC; ICA_PARTNUM: $$2075017$$ECJ1VB1E104K; MFG: Yageo; Notes: DNI; Part Number: CC0402KRX7R9BB272; Rating: 50V; Rating/Tolerance: 50V,10%; Tolerance: 10%; Type: X7R
J500 = FMC_400POS_CONNECTOR: MFG: Samtec; PART NUMBER: SEAM-40-11.0-S-10-2-A-K-TR
L1-L4 = FERRITE_L: Ferrite; CCA ITEM: 59; CURRENT: 2A; DigiKey Part Number: 490-1054-1-ND; ICA_MFR_NAME: MURATA; ICA_PARTNUM: $$1507311$$BLM21PG221SG; MFG: MURATA; Part Number: BLM21PG221SN1D; Rating: 2A, 50mOhm; Tolerance: 25%
R1 = R: Resistor; CCA ITEM: ?; DNI: DNI; DigiKey Part Number: P1.0KGCT-ND; Do Not Install: Do Not Install; MFG: Panasonic; Notes: DNI; Part Number: ERJ-3GEYJ102V; Rating: 1/10W; Tolerance: 5%
R2 R15 R21 R41 R49 R52 = R: Resistor; CCA ITEM: ?; DigiKey Part Number: P10KGCT-ND; MFG: Panasonic; Part Number: ERJ-3GEYJ103V; Rating: 1/10W; Tolerance: 5%
R3 = R: Resistor; CCA ITEM: ?; DNI: DNI; DigiKey Part Number: P10KGCT-ND; Do Not Install: Do Not Install; MFG: Panasonic; Notes: DNI; Part Number: ERJ-3GEYJ103V; Rating: 1/10W; Tolerance: 5%
R4 R28 = RESISTOR_dsize: Resistor; CCA ITEM: 110; DigiKey Part Number: P0.0GCT-ND; ICA_MFR_NAME: PANASONIC; ICA_PARTNUM: $$1785380$$ERJ-3GSYJ330V; Mfg: Panasonic; Part Number: ERJ-3GEY0R00V; RATING/TOLERANCE: <RATING/TOLERANCE>; Rating: 1/10W
TP1 TP2 TP9 TP10 TP23-TP28 = Testpoint: Test point; Part Number: TMP-543
C10-C12 C23 C26 = CAP_NP_dsize: Capacitor; DigiKey Part Number: 478-1627-1-ND; ESR: <ESR>; Mfg: AVX; Part Number: 12103D106KAT2A; Rating: 25V; Rating/Tolerance: 25V,10%; Tolerance: 10%; Type: X5R; VOLTAGE: 25V
C13 C19 C20 C22 = CAP_NP_dsize: Capacitor; DigiKey Part Number: 478-5142-1-ND; Mfg: AVX; Part Number: 06033D105KAT2A; Rating: 25V; Tolerance: 10%; Type: X5R; VOLTAGE: 25V
C14 = CAP_NP_dsize: Capacitor; DigiKey Part Number: 1276-1169-1-ND; Mfg: Samsung; Part Number: CL21B102KCANNNC; Rating: 50V; Tolerance: 10%; Type: X7R; VOLTAGE: 100V
C15 = CAP_NP_dsize: Capacitor; DigiKey Part Number: 490-3105-1-ND; Mfg: Murata; Part Number: GJM1555C1H6R2CB01D; Rating: 50V; TOLERANCE: 5%; Type: NP0; VOLTAGE: 50V
C16 = CAP_NP_dsize: Capacitor; DigiKey Part Number: 587-1378-1-ND; ESR: <ESR>; Mfg: Samsung; Rating: 16V; Rating/Tolerance: 16V,20%; Tolerance: 20%; Type: X5R; VOLTAGE: 16V; part number: CL32A226MOJNNNE
C17 C24 C27 = CAP_NP_dsize: Capacitor; DigiKey Part Number: 478-3351-1-ND; ESR: 0.1 OHM; ICA_MFR_NAME: NIC; ICA_PARTNUM: $$2075017$$NMC1206X7R104K50; Mfg: AVX; Part Number: 08055C104MAT2A; Rating: 50V; Rating/Tolerance: 50V, 20%; Tolerance: 20%; Type: X7R; VOLTAGE: 50V
C18 C21 = CAP_NP_dsize: Capacitor; DigiKey Part Number: 478-3351-1-ND; ESR: 0.1 OHM; ICA_MFR_NAME: NIC; ICA_PARTNUM: $$2075017$$NMC1206X7R104K50; Mfg: AVX; Part Number: 08055C104MAT2A; Rating: 50V; Rating/Tolerance: 50V; Tolerance: 20%; Type: X7R; VOLTAGE: 50V
C25 = CAP_NP_dsize: Capacitor; DigiKey Part Number: 445-2512-1-ND; Mfg: TDK; Part Number: C2012X8R1E224K; Rating: 25V; Tolerance: 10%; Type: X8R; VOLTAGE: 25V
C28 = CAP_NP_dsize: Capacitor; DNI: DNI; DigiKey Part Number: 311-1033-1-ND; Do Not Install: Do Not Install; ESR: <ESR>; ICA_MFR_NAME: PANASONIC; ICA_PARTNUM: $$2075017$$ECJ1VB1E104K; MFG: Yageo; Notes: DNI; Part Number: CC0402KRX7R9BB272; Rating: 50V; Rating/Tolerance: 50V,10%; Tolerance: 10%; Type: X7R; VOLTAGE: 50V
C104 C105 = CAP_NP_dsize: Capacitor; DNI: DNI; DigiKey Part Number: 478-1627-1-ND; ESR: <ESR>; Mfg: AVX; Notes: DNI; Part Number: 12103D106KAT2A; Rating: 25V; Rating/Tolerance: 25V,10%; Tolerance: 10%; Type: X5R; VOLTAGE: 25V
D1 = DIODE_ZENER: Diode, Zener; DigiKey Part Number: DZ2J03300LCT-ND; Mfg: ON Semiconductor; Part Number: MM3Z3V3B
D2 = DIODE_ZENER: DIODE Zener; CCA ITEM: 9; DigiKey Part Number: 1SMB5926BT3GOSCT-ND; MFG: ON Semiconductor; Part Number: 1SMB5926BT3G; RATING: 3W; RATING/TOLERANCE: 5%; Tolerance: 5%
D3 = DIODE_SCHOTTKY_dsize: Diode Schottky; DigiKey Part Number: 497-7538-1-ND; Mfg: STM; Rating: 40V 0.5A
D4 D5 = BAT54SW_0: Diode Schottky; DigiKey Part Number: 568-1615-1-ND; ICA_MFR_NAME: PHILIPS SEMICONDUCTOR; ICA_PARTNUM: $$1491280$$BAT54SW; Mfg: NXP; Part Number: BAT54SW,115; Rating: 30V
J3 = CONN_HEADER_2POS_.100_SNGL_SMD: Connector; DNI: DNI; DigiKey Part Number: SAM8980-ND; Do Not Install: Do Not Install; Mfg: Samtec; Notes: DNI
L5 = INDUCTOR: Inductor; CCA ITEM: 12; DigiKey Part Number: Mouser 994-LPS4018-222MRB; ICA_MFR_NAME: STEWARD; ICA_PARTNUM: $$731362$$MI0603J680R-10; MFG: COILCRAFT; Part Number: LPS4018-472MRC; RATING: 1.3 A, 0.125Ohm; TOLERANCE: 20%
PCB1 = DLP028_28: Board Instance; MFG: Any; Part Number: DLP104
Q1 = FDMA910PZ: MOSFET, P-Chan; DigiKey Part Number: FDMA910PZCT-ND; MFG: FAIRCHILD; Rating: 20 mOhm @ 9.4A, 4.5V
Q2 = 2N2222A: Transistor, NPN; DigiKey Part Number: MMBT2222A-FDICT-ND; MFG: FAIRCHILD; Part Number: MMBT2222A-7-F; RATING: 40V, 600mA
Q3 = 2N7002_SOT: MOSFET, N-Chan; DigiKey Part Number: 2N7002LT1GOSCT-ND; MFG: ON Semicondutor; PART NUMBER: 2N7002L
R5 R6 R9-R12 = R: Resistor; ALT_SYMBOLS: 0402-1MM; DigiKey Part Number: P12ACT-ND; ICA_MFR_NAME: PANASONIC; ICA_PARTNUM: $$1785048$$ERJ-3GSYJ102; MFG: PANASONIC; Part Number: ERJ-6GEYJ120V; RATING: 1/8W; TOLERANCE: 5%
R7 = R: Resistor; ALT_SYMBOLS: 0402-1MM; DigiKey Part Number: P2.2KJCT-ND; ICA_MFR_NAME: PANASONIC; ICA_PARTNUM: $$1785048$$ERJ-3GSYJ102; MFG: PANASONIC; Part Number: ERJ-2GEJ222X; RATING: 1/10W; TOLERANCE: 5%
R8 R17 R29 R30 = R: Resistor; ALT_SYMBOLS: 0402-1MM; DigiKey Part Number: P1.0KJCT-ND; ICA_MFR_NAME: PANASONIC; ICA_PARTNUM: $$1785048$$ERJ-3GSYJ102; MFG: PANASONIC; Part Number: ERJ-2GEJ102X; RATING: 1/10W; TOLERANCE: 5%
R13 = RESISTOR_dsize: Resistor; DNI: DNI; DigiKey Part Number: P0.0GCT-ND; Do Not Install: Do Not Install; ICA_MFR_NAME: YAGEO; ICA_PARTNUM: $$482834$$RC0603JRF070R0; Mfg: Panasonic; Part Number: ERJ-3GEY0R00V; Rating: 1/10W
R14 = RESISTOR_dsize: Resistor; DigiKey Part Number: P432KHCT-ND; Mfg: Panasonic; Part Number: ERJ-3EKF4323V; Rating: 1/10W; Tolerance: 1%
R16 = R: Resistor; DigiKey Part Number: P2.0KJCT-ND; ICA_MFR_NAME: PANASONIC; ICA_PARTNUM: $$1785048$$ERJ-3GSYJ102; MFG: PANASONIC; Part Number: ERJ-2GEJ202X; RATING: 1/10W; SOURCE: DIGI P2.0KJCT-ND; TOLERANCE: 5%
R18 = RES: Resistor; DigiKey Part Number: 311-15.0KHRCT-ND; ICA_MFR_NAME: YAGEO; ICA_PARTNUM: $$2140285$$RC0603FR-0715KL; Mfg: Yageo; Part Number: RC0603FR-0715KL; Rating: 1/10W; Tolerance: 1%
R19 = RESISTOR_dsize: Resistor; DigiKey Part Number: P56.2KHCT-ND; Mfg: Panasonic; Part Number: ERJ-3EKF5622V; Rating: 1/10W; Tolerance: 1%
R20 = RESISTOR: Resistor; DigiKey Part Number: P10KJCT-ND; Mfg: Panasonic; Part Number: ERJ-2GEJ103X; Rating: 1/10W; Tolerance: 5%
R22 = R: Resistor; DigiKey Part Number: P53.6KDBCT-ND; ICA_MFR_NAME: PANASONIC; ICA_PARTNUM: $$1784362$$ERJ-3GEYJ753; Mfg: Panasonic; Part Number: ERA-3AEB5362V; Rating: 1/10W; Tolerance: 0.1%
R23 = RESISTOR_dsize: Resistor; DigiKey Part Number: A102305TR-ND; Mfg: TE Connectivity; Part Number: CPF0603B620KE1; Rating: 1/16W; Tolerance: 0.1%
R24 = RESISTOR: Resistor; DigiKey Part Number: P33KJCT-ND; Mfg: Panasonic; Part Number: ERJ-2GEJ332X; Rating: 1/10W; tolerance: 5%
R25 = RESISTOR_dsize: Resistor; DigiKey Part Number: RR12P820KDCT-ND; Mfg: Susumu; Part Number: RR1220P-824-D; Rating: 1/10W; Tolerance: 0.5%
R26 = RESISTOR_dsize: Resistor; DigiKey Part Number: 311-59KDCT-ND; Mfg: Yageo; Part Number: RT0603DRD0759KL; Rating: 1/10W; Tolerance: 0.5%
R27 = RESISTOR: Resistor; DigiKey Part Number: P33KJCT-ND; Mfg: Panasonic; Part Number: ERJ-2GEJ333X; Rating: 1/10W; Tolerance: 5%
TP3-TP8 = Testpoint: Test Point; Part Number: TMP-543
U1 = LP38513S-1.8_NOPB: IC, Voltage Regulator; DigiKey Part Number: 296-39799-5-ND; MFG: TI
U2-U5 = N-FET_2: MOSFET, N-Channel; DigiKey Part Number: FDV303NCT-ND; MFG: FAIRCHILD SEMI; Part Number: FDV303N; RATING: 20V; TOLERANCE: 460MW
U6 = N-FET_1: MOSFET, N-Channel; DigiKey Part Number: BSS84CT-ND; MFG: FAIRCHILD SEMI; RATING: 50V; TOLERANCE: 130MA
U7 = TPS65145_11: IC Voltage Regulator; DigiKey Part Number: 296-19000-1-ND; Mfg: TI; Part Number: TPS65145PWP
U1000 = DLP028_30: DMD Instnace; MFG: Any
C29 C31-C44 C46-C54 C56-C65 C67-C76 C78-C87 C89-C103 = CAP_NP_dsize: Capacitor; DigiKey Part Number: 445-1316-1-ND; ESR: <ESR>; ICA_MFR_NAME: PANASONIC; ICA_PARTNUM: $$2075017$$ECJ1VB1E104K; Mfg: TDK; Part Number: C1608X7R1E104K; Rating: 25V; Rating/Tolerance: 25V,10%; Tolerance: 10%; Type: X7R
C30 = CAP_NP_dsize: Capacitor; DigiKey Part Number: 478-1089-1-ND; Mfg: AVX; Part Number: 04025C101KAT2A; Rating: 50V; Type: X7R
J4 = Conn_4: Connector, 4 Pin; DigiKey Part Number: WM7622CT-ND; MFG: Molex; Part Number: 053261-0471
MT1-MT6 = Testpoint: Test point
R31 R32 = R: Resistor; CCA ITEM: ?; DigiKey Part Number: P1.0KGCT-ND; Do Not Install: Do Not Install; MFG: Panasonic; Part Number: ERJ-3GEYJ102V; Rating: 1/10W; Tolerance: 5%
R33 R34 = R: Resistor; CCA ITEM: 13; DigiKey Part Number: P51JCT-ND; MFG: Panasonic; Part Number: ERJ-2GEJ510X; Rating: 1/10W; Tolerance: 5%
R35-R40 R42-R48 R50 R51 = R: Resistor; CCA ITEM: 13; DigiKey Part Number: YAG1264CT-ND; MFG: Yageo; Part Number: RC0402FR-0733RP; Rating: 1/16W; Tolerance: 1%
U8 = DMD_0P5_TRP_S410_0
U9 = TMP411: IC, Temp Sensor; DigiKey Part Number: 296-22015-1-ND; MFG: TI; Part Number: TMP411ADGK
U10 U11 = SN74AVCH8T245RHLR: IC, Level Translator; DigiKey Part Number: 296-22015-1-ND; MFG: TI
U12 = SN74AVCH4T245RGYR: IC, Level Translator; DigiKey Part Number: 296-22015-1-ND; MFG: TI
C45 = CAP_NP_dsize: Capacitor; DigiKey Part Number: 478-1627-1-ND; ESR: <ESR>; Mfg: AVX; Part Number: 12103D106KAT2A; Rating: 25V; Rating/Tolerance: 25V,10%; Tolerance: 10%; Type: X5R
C55 C66 C77 C88 = CAP_NP_dsize: Capacitor; DigiKey Part Number: 1276-1085-1-ND; ESR: <ESR>; ICA_MFR_NAME: PANASONIC; ICA_PARTNUM: $$2075017$$ECJ1VB1E104K; Mfg: Samsung; Part Number: CL10A225KP8NNNC; Rating: 10V; Rating/Tolerance: 10V,10%; Tolerance: 20%; Type: X5R
HW1000 = DLP028_31: Mounting Clamp; Mfg: Any; Part Number: N/A
HW1001 = DLP028_34: Mounting Insulator; Mfg: Any; Part Number: N/A
HW1002 = DLP028_33: Mounting Interface; Mfg: ANY; Part Number: N/A
HW1003 = DLP028_35: Mounting Standoff; Mfg: Any; Part Number: N/A
HW1005 = DLP028_36: Mounting Washer; Mfg: McMaster-Carr; Part Number: 4061T114

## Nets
GND: C1.2 C2.2 C3.2 C4.2 C5.2 C6.2 C7.2 C8.2 C9.2 C10.1 C11.1 C12.1 C14.1 C16.2 C17.2 C20.2 C22.2 C23.1 C24.2 C25.2 C26.1 C27.2 C28.2 C29.2 C31.2 C32.2 C33.2 C34.2 C35.2 C36.2 C37.2 C38.2 C39.2 C40.2 C41.2 C42.2 C43.2 C44.2 C45.1 C46.2 C47.2 C48.2 C49.2 C50.2 C51.2 C52.2 C53.2 C54.2 C55.2 C56.2 C57.2 C58.2 C59.2 C60.2 C61.2 C62.2 C63.2 C64.2 C65.2 C66.2 C67.2 C68.2 C69.2 C70.2 C71.2 C72.2 C73.2 C74.2 C75.2 C76.2 C77.2 C78.2 C79.2 C80.2 C81.2 C82.2 C83.2 C84.2 C85.2 C86.2 C87.2 C88.2 C89.2 C90.2 C91.2 C92.2 C93.2 C94.2 C95.2 C96.2 C97.2 C98.2 C99.2 C100.2 C101.2 C102.2 C103.2 C104.1 C105.1 D2.2(ANODE) D4.2(K2) J4.4 J500.A01(GND) J500.A03(DP1_M2C_N) J500.A04(GND) J500.A05(GND) J500.A07(DP2_M2C_N) J500.A08(GND) J500.A09(GND) J500.A11(DP3_M2C_N) J500.A12(GND) J500.A13(GND) J500.A15(DP4_M2C_N) J500.A16(GND) J500.A17(GND) J500.A19(DP5_M2C_N) J500.A20(GND) J500.A21(GND) J500.A23(DP1_C2M_N) J500.A24(GND) J500.A25(GND) J500.A27(DP2_C2M_N) J500.A28(GND) J500.A29(GND) J500.A31(DP3_C2M_N) J500.A32(GND) J500.A33(GND) J500.A35(DP4_C2M_N) J500.A36(GND) J500.A37(GND) J500.A39(DP5_C2M_N) J500.A40(GND) J500.B02(GND) J500.B03(GND) J500.B05(DP9_M2C_N) J500.B06(GND) J500.B07(GND) J500.B09(DP8_M2C_N) J500.B10(GND) J500.B11(GND) J500.B13(DP7_M2C_N) J500.B14(GND) J500.B15(GND) J500.B18(GND) J500.B19(GND) J500.B22(GND) J500.B23(GND) J500.B26(GND) J500.B27(GND) J500.B30(GND) J500.B31(GND) J500.B33(DP7_C2M_N) J500.B34(GND) J500.B35(GND) J500.B37(DP6_C2M_N) J500.B38(GND) J500.B39(GND) J500.C01(GND) J500.C03(DP0_C2M_N) J500.C04(GND) J500.C05(GND) J500.C07(DP0_M2C_N) J500.C08(GND) J500.C09(GND) J500.C12(GND) J500.C13(GND) J500.C16(GND) J500.C17(GND) J500.C20(GND) J500.C21(GND) J500.C24(GND) J500.C25(GND) J500.C28(GND) J500.C29(GND) J500.C32(GND) J500.C33(GND) J500.C36(GND) J500.C38(GND) J500.C40(GND) J500.D02(GND) J500.D03(GND) J500.D06(GND) J500.D07(GND) J500.D10(GND) J500.D13(GND) J500.D16(GND) J500.D19(GND) J500.D22(GND) J500.D25(GND) J500.D28(GND) J500.D37(GND) J500.D39(GND) J500.E01(GND) J500.E04(GND) J500.E05(GND) J500.E08(GND) J500.E11(GND) J500.E14(GND) J500.E17(GND) J500.E20(GND) J500.E23(GND) J500.E26(GND) J500.E29(GND) J500.E32(GND) J500.E35(GND) J500.E38(GND) J500.E40(GND) J500.F02(GND) J500.F03(GND) J500.F06(GND) J500.F09(GND) J500.F12(GND) J500.F15(GND) J500.F18(GND) J500.F21(GND) J500.F24(GND) J500.F27(GND) J500.F30(GND) J500.F33(GND) J500.F36(GND) J500.F39(GND) J500.G01(GND) J500.G04(GND) J500.G05(GND) J500.G08(GND) J500.G11(GND) J500.G14(GND) J500.G17(GND) J500.G20(GND) J500.G23(GND) J500.G26(GND) J500.G29(GND) J500.G32(GND) J500.G35(GND) J500.G38(GND) J500.G40(GND) J500.H03(GND) J500.H06(GND) J500.H09(GND) J500.H12(GND) J500.H15(GND) J500.H18(GND) J500.H21(GND) J500.H24(GND) J500.H27(GND) J500.H30(GND) J500.H33(GND) J500.H36(GND) J500.H39(GND) J500.J01(GND) J500.J04(GND) J500.J05(GND) J500.J08(GND) J500.J11(GND) J500.J14(GND) J500.J17(GND) J500.J20(GND) J500.J23(GND) J500.J26(GND) J500.J29(GND) J500.J32(GND) J500.J35(GND) J500.J38(GND) J500.J40(GND) J500.K02(GND) J500.K03(GND) J500.K06(GND) J500.K09(GND) J500.K12(GND) J500.K15(GND) J500.K18(GND) J500.K21(GND) J500.K24(GND) J500.K27(GND) J500.K30(GND) J500.K33(GND) J500.K36(GND) J500.K39(GND) MT1.1 MT2.1 MT3.1 MT4.1 MT5.1 MT6.1 Q2.1(EMITTER) R12.2 R15.1 R19.2 R24.2 R26.1 R41.1 R49.1 R52.1 TP2.1 TP9.1 TP10.1 TP27.1 TP28.1 U1.3(GND) U1.6(GND(TAB)) U3.2(S) U4.2(S) U5.2(S) U6.1(G) U7.7(PGND) U7.8(PGND) U7.11(GND) U7.19(GND) U7.23(ENR) U7.25(POWER_PAD) U8.A13(VSS(GND)) U8.A22(VSS(GND)) U8.A23(VSS(GND)) U8.B3(VSS(GND)) U8.B6(VSS(GND)) U8.B9(VSS(GND)) U8.B12(VSS(GND)) U8.B14(VSS(GND)) U8.B15(VSS(GND)) U8.B20(VSS(GND)) U8.B23(VSS(GND)) U8.B26(VSS(GND)) U8.B29(VSS(GND)) U8.C5(VSS(GND)) U8.C19(VSS(GND)) U8.C21(VSS(GND)) U8.D2(VSS(GND)) U8.G2(VSS(GND)) U8.J28(VSS(GND)) U8.K3(VSS(GND)) U8.L28(VSS(GND)) U8.L30(VSS(GND)) U8.M3(VSS(GND)) U8.P27(VSS(GND)) U8.P29(VSS(GND)) U8.U29(VSS(GND)) U8.V21(VSS(GND)) U8.V23(VSS(GND)) U8.V26(VSS(GND)) U8.W2(VSS(GND)) U8.W5(VSS(GND)) U8.W8(VSS(GND)) U8.W12(VSS(GND)) U8.W16(VSS(GND)) U8.W18(VSS(GND)) U8.W22(VSS(GND)) U8.W25(VSS(GND)) U8.W28(VSS(GND)) U8.W30(VSS(GND)) U8.Z21(VSS(GND)) U8.Z22(VSS(GND)) U8.Z24(VSS(GND)) U9.5(GND) U10.11(GND) U10.12(GND) U10.13(GND) U10.22(OEZ) U11.11(GND) U11.12(GND) U11.13(GND) U11.22(OEZ) U12.8(GND) U12.9(GND) U12.14(2OEZ)
P12V: J500.C35(12P0V) J500.C37(12P0V)
3P3VAUX: J500.D32(3P3VAUX)
ADDR_0: R37.2 U8.Z13(A0)
ADDR_1: R38.2 U8.W13(A1)
ADDR_2: R39.2 U8.V10(A2)
ADDR_3: R40.2 U8.W14(A3)
C1+: C18.1 U7.16(C1+)
C1-: C18.2 U7.17(C1-)
C2+: Q3.2(SOURCE) U7.14(C2+)
C2-: C21.2 U7.15(C2-/MODE)
COMP: R18.2 U7.22(COMP)
DAD_OEZ: J500.B04(DP9_M2C_P) R1.1 R4.2
DADADDR_0: J500.A14(DP4_M2C_P) U10.5(A3)
DADADDR_1: J500.A18(DP5_M2C_P) U10.6(A4)
DADADDR_2: J500.A22(DP1_C2M_P) U10.7(A5)
DADADDR_3: J500.A26(DP2_C2M_P) U10.8(A6)
DADIRQZ: J500.B08(DP8_M2C_P) R51.2
DADMODE_0: J500.A06(DP2_M2C_P) U10.4(A2)
DADMODE_1: J500.A10(DP3_M2C_P)
DADOEZ: C5.1 R4.1 U11.5(A3)
DADSEL_0: J500.A30(DP3_C2M_P) U11.3(A1)
DADSEL_1: J500.A34(DP4_C2M_P) U11.4(A2)
DADSTRB: J500.A38(DP5_C2M_P) U10.3(A1)
DMD_EN_OFFSET: U8.C9(EN_OFFSET) U12.6(2A1)
DMD_P1P8V: C10.2 C31.1 C32.1 C35.1 C36.1 C37.1 C45.2 C46.1 C47.1 C48.1 C49.1 C50.1 C51.1 C52.1 C53.1 C54.1 C55.1 C56.1 C57.1 C58.1 C59.1 C60.1 C61.1 C62.1 C63.1 C64.1 C65.1 C66.1 C67.1 C68.1 C69.1 C70.1 C71.1 C72.1 C73.1 C74.1 C75.1 C76.1 C77.1 C78.1 C79.1 C80.1 C81.1 C82.1 C83.1 C84.1 C85.1 C86.1 C87.1 C88.1 C89.1 C90.1 R27.1 R29.1 R30.1 TP3.1 U1.4(VOUT) U8.A7(VCC) U8.A24(VCC) U8.B5(VCC) U8.B10(VCC) U8.B13(VCC) U8.B16(VCC) U8.B19(VCC) U8.B22(VCC) U8.B28(VCC) U8.C17(VCC) U8.C20(VCC) U8.D4(VCC) U8.J29(VCC) U8.K2(VCC) U8.L29(VCC) U8.M2(VCC) U8.N27(VCC) U8.U27(VCC) U8.V13(VCC) U8.V15(VCC) U8.V22(VCC) U8.W3(VCC) U8.W17(VCC) U8.W21(VCC) U8.W26(VCC) U8.W29(VCC) U8.Z7(VCC) U8.Z18(VCC) U8.Z23(VCC) U8.Z29(VCC) U10.23(VCCB) U10.24(VCCB) U11.23(VCCB) U11.24(VCCB) U12.1(VCCA) U12.2(1DIR) U12.3(2DIR)
DMD_P3P3V: C2.1 C3.1 C7.1 C9.1 C11.2 C12.2 C29.1 C33.1 C34.1 C38.1 C104.2 C105.2 J3.1 J4.3 L1.2 L2.2 L3.1 L4.1 L5.1 R1.2 R2.2 R3.2 R8.1 R31.2 R32.2 TP1.1 U1.1(EN) U1.2(VIN) U7.4(Vin) U9.1(VCC) U10.1(VCCA) U10.2(DIR) U11.1(VCCA) U11.2(DIR) U12.16(VCCB)
DMD_SCP_CLK: R45.2 U8.A10(SCPCLK)
DMD_SCP_DI: R29.2 U8.A11(SCPDO) U12.4(1A1)
DMD_SCP_DO: R46.2 U8.A12(SCPDI)
DMDRSTZ: J500.A02(DP1_M2C_P) R2.1 U11.9(A7)
DRV: C19.2 U7.18(DRV)
DRV_1: C19.1 D4.3(K1)
DRV_D: C13.1 D5.3(K1)
EN_OFFSET: J3.2 R15.2 R20.1 TP5.1 U3.1(G) U7.24(EN) U12.11(2B1)
FB1: C15.2 R14.2 R19.1 U7.1(FB1)
FB2: R22.2 R23.1 U7.21(FB2)
FB3: R25.2 R26.2 U7.12(FB3)
IRQZ: R30.2 U8.V16(IRQZ) U12.7(2A2)
M_DCLKA_N: J500.K05(CLK2_M2C_N) U8.D27(DCLK_CN)
M_DCLKA_P: J500.K04(CLK2_M2C_P) U8.E27(DCLK_CP)
M_DCLKB_N: J500.J03(CLK3_M2C_N) U8.N29(DCLK_DN)
M_DCLKB_P: J500.J02(CLK3_M2C_P) U8.N30(DCLK_DP)
M_DDA00_N: J500.D21(LA17_N_CC) U8.H27(D_CN_0)
M_DDA00_P: J500.D20(LA17_P_CC) U8.J27(D_CP_0)
M_DDA01_N: J500.C23(LA18_N_CC) U8.A20(D_CN_1)
M_DDA01_P: J500.C22(LA18_P_CC) U8.A19(D_CP_1)
M_DDA02_N: J500.H23(LA19_N) U8.H28(D_CN_2)
M_DDA02_P: J500.H22(LA19_P) U8.H29(D_CP_2)
M_DDA03_N: J500.G22(LA20_N) U8.K28(D_CN_3)
M_DDA03_P: J500.G21(LA20_P) U8.K27(D_CP_3)
M_DDA04_N: J500.H26(LA21_N) U8.K30(D_CN_4)
M_DDA04_P: J500.H25(LA21_P) U8.K29(D_CP_4)
M_DDA05_N: J500.G25(LA22_N) U8.C23(D_CN_5)
M_DDA05_P: J500.G24(LA22_P) U8.C22(D_CP_5)
M_DDA06_N: J500.D24(LA23_N) U8.G27(D_CN_6)
M_DDA06_P: J500.D23(LA23_P) U8.F27(D_CP_6)
M_DDA07_N: J500.H29(LA24_N) U8.J30(D_CN_7)
M_DDA07_P: J500.H28(LA24_P) U8.H30(D_CP_7)
M_DDA08_N: J500.G28(LA25_N) U8.B24(D_CN_8)
M_DDA08_P: J500.G27(LA25_P) U8.B25(D_CP_8)
M_DDA09_N: J500.D27(LA26_N) U8.A21(D_CN_9)
M_DDA09_P: J500.D26(LA26_P) U8.B21(D_CP_9)
M_DDA10_N: J500.C27(LA27_N) U8.A27(D_CN_10)
M_DDA10_P: J500.C26(LA27_P) U8.B27(D_CP_10)
M_DDA11_N: J500.H32(LA28_N) U8.C29(D_CN_11)
M_DDA11_P: J500.H31(LA28_P) U8.C28(D_CP_11)
M_DDA12_N: J500.G31(LA29_N) U8.A26(D_CN_12)
M_DDA12_P: J500.G30(LA29_P) U8.A25(D_CP_12)
M_DDA13_N: J500.H35(LA30_N) U8.C25(D_CN_13)
M_DDA13_P: J500.H34(LA30_P) U8.C24(D_CP_13)
M_DDA14_N: J500.G34(LA31_N) U8.A29(D_CN_14)
M_DDA14_P: J500.G33(LA31_P) U8.A28(D_CP_14)
M_DDA15_N: J500.H38(LA32_N) U8.C30(D_CN_15)
M_DDA15_P: J500.H37(LA32_P) U8.B30(D_CP_15)
M_DDB00_N: J500.K26(HB00_CC_N) U8.V25(D_DN_0)
M_DDB00_P: J500.K25(HB00_CC_P) U8.V24(D_DP_0)
M_DDB01_N: J500.J25(HB01_N) U8.V28(D_DN_1)
M_DDB01_P: J500.J24(HB01_P) U8.V29(D_DP_1)
M_DDB02_N: J500.F23(HB02_N) U8.T30(D_DN_2)
M_DDB02_P: J500.F22(HB02_P) U8.T29(D_DP_2)
M_DDB03_N: J500.E22(HB03_N) U8.V27(D_DN_3)
M_DDB03_P: J500.E21(HB03_P) U8.W27(D_DP_3)
M_DDB04_N: J500.F26(HB04_N) U8.U30(D_DN_4)
M_DDB04_P: J500.F25(HB04_P) U8.V30(D_DP_4)
M_DDB05_N: J500.E25(HB05_N) U8.W23(D_DN_5)
M_DDB05_P: J500.E24(HB05_P) U8.W24(D_DP_5)
M_DDB06_N: J500.K29(HB06_N_CC) U8.R27(D_DN_6)
M_DDB06_P: J500.K28(HB06_P_CC) U8.T27(D_DP_6)
M_DDB07_N: J500.J28(HB07_N) U8.T28(D_DN_7)
M_DDB07_P: J500.J27(HB07_P) U8.U28(D_DP_7)
M_DDB08_N: J500.F29(HB08_N) U8.V20(D_DN_8)
M_DDB08_P: J500.F28(HB08_P) U8.V19(D_DP_8)
M_DDB09_N: J500.E28(HB09_N) U8.R28(D_DN_9)
M_DDB09_P: J500.E27(HB09_P) U8.R29(D_DP_9)
M_DDB10_N: J500.K32(HB10_N) U8.L27(D_DN_10)
M_DDB10_P: J500.K31(HB10_P) U8.M27(D_DP_10)
M_DDB11_N: J500.J31(HB11_N) U8.N28(D_DN_11)
M_DDB11_P: J500.J30(HB11_P) U8.P28(D_DP_11)
M_DDB12_N: J500.F32(HB12_N) U8.M28(D_DN_12)
M_DDB12_P: J500.F31(HB12_P) U8.M29(D_DP_12)
M_DDB13_N: J500.E31(HB13_N) U8.V18(D_DN_13)
M_DDB13_P: J500.E30(HB13_P) U8.V17(D_DP_13)
M_DDB14_N: J500.K35(HB14_N) U8.Z26(D_DN_14)
M_DDB14_P: J500.K34(HB14_P) U8.Z25(D_DP_14)
M_DDB15_N: J500.J34(HB15_N) U8.Z28(D_DN_15)
M_DDB15_P: J500.J33(HB15_P) U8.Z27(D_DP_15)
M_SCTRLA_N: J500.G37(LA33_N) U8.C26(SCTRL_CN)
M_SCTRLA_P: J500.G36(LA33_P) U8.C27(SCTRL_CP)
M_SCTRLB_N: J500.F35(HB16_N) U8.P30(SCTRL_DN)
M_SCTRLB_P: J500.F34(HB16_P) U8.R30(SCTRL_DP)
MODE_0: R36.2 U8.W9(MODE0)
OEZ: R44.2 U8.W15(OEZ)
P3P3V1: C1.1 J500.C39(3P3V) L1.1
P3P3V2: C4.1 J500.D36(3P3V) L2.1
P3P3V3: C6.1 J500.D38(3P3V) L3.2
P3P3V4: C8.1 J500.D40(3P3V) L4.2
PG: C28.1 R28.1 U7.10(PG)
PG_OFFSET: R27.2 R28.2 TP8.1 U8.A9(PG_OFFSET)
REF: C25.1 R22.1 U7.20(REF)
RES0: J500.B40(RES0)
RES1: J500.B01(RES1)
RSTZ: R48.2 U8.A8(PWRDNZ)
S_DCLKA_N: J500.H05(CLK0_M2C_N) U8.H2(DCLK_AN)
S_DCLKA_P: J500.H04(CLK0_M2C_P) U8.H1(DCLK_AP)
S_DCLKB_N: J500.G03(CLK1_M2C_N) U8.V6(DCLK_BN)
S_DCLKB_P: J500.G02(CLK1_M2C_P) U8.V7(DCLK_BP)
S_DDA00_N: J500.G07(LA00_N_CC) U8.C6(D_AN_0)
S_DDA00_P: J500.G06(LA00_P_CC) U8.C7(D_AP_0)
S_DDA01_N: J500.D09(LA01_N_CC) U8.C3(D_AN_1)
S_DDA01_P: J500.D08(LA01_P_CC) U8.C2(D_AP_1)
S_DDA02_N: J500.H08(LA02_N) U8.E1(D_AN_2)
S_DDA02_P: J500.H07(LA02_P) U8.E2(D_AP_2)
S_DDA03_N: J500.G10(LA03_N) U8.C4(D_AN_3)
S_DDA03_P: J500.G09(LA03_P) U8.B4(D_AP_3)
S_DDA04_N: J500.H11(LA04_N) U8.D1(D_AN_4)
S_DDA04_P: J500.H10(LA04_P) U8.C1(D_AP_4)
S_DDA05_N: J500.D12(LA05_N) U8.B8(D_AN_5)
S_DDA05_P: J500.D11(LA05_P) U8.B7(D_AP_5)
S_DDA06_N: J500.C11(LA06_N) U8.F4(D_AN_6)
S_DDA06_P: J500.C10(LA06_P) U8.E4(D_AP_6)
S_DDA07_N: J500.H14(LA07_N) U8.E3(D_AN_7)
S_DDA07_P: J500.H13(LA07_P) U8.D3(D_AP_7)
S_DDA08_N: J500.G13(LA08_N) U8.C11(D_AN_8)
S_DDA08_P: J500.G12(LA08_P) U8.C12(D_AP_8)
S_DDA09_N: J500.D15(LA09_N) U8.F3(D_AN_9)
S_DDA09_P: J500.D14(LA09_P) U8.F2(D_AP_9)
S_DDA10_N: J500.C15(LA10_N) U8.K4(D_AN_10)
S_DDA10_P: J500.C14(LA10_P) U8.J4(D_AP_10)
S_DDA11_N: J500.H17(LA11_N) U8.H3(D_AN_11)
S_DDA11_P: J500.H16(LA11_P) U8.G3(D_AP_11)
S_DDA12_N: J500.G16(LA12_N) U8.J3(D_AN_12)
S_DDA12_P: J500.G15(LA12_P) U8.J2(D_AP_12)
S_DDA13_N: J500.D18(LA13_N) U8.C13(D_AN_13)
S_DDA13_P: J500.D17(LA13_P) U8.C14(D_AP_13)
S_DDA14_N: J500.C19(LA14_N) U8.A5(D_AN_14)
S_DDA14_P: J500.C18(LA14_P) U8.A6(D_AP_14)
S_DDA15_N: J500.H20(LA15_N) U8.A3(D_AN_15)
S_DDA15_P: J500.H19(LA15_P) U8.A4(D_AP_15)
S_DDB00_N: J500.F05(HA00_N_CC) U8.N4(D_BN_0)
S_DDB00_P: J500.F04(HA00_P_CC) U8.M4(D_BP_0)
S_DDB01_N: J500.E03(HA01_N_CC) U8.Z11(D_BN_1)
S_DDB01_P: J500.E02(HA01_P_CC) U8.Z12(D_BP_1)
S_DDB02_N: J500.K08(HA02_N) U8.W4(D_BN_2)
S_DDB02_P: J500.K07(HA02_P) U8.Z4(D_BP_2)
S_DDB03_N: J500.J07(HA03_N) U8.W10(D_BN_3)
S_DDB03_P: J500.J06(HA03_P) U8.Z10(D_BP_3)
S_DDB04_N: J500.F08(HA04_N) U8.L1(D_BN_4)
S_DDB04_P: J500.F07(HA04_P) U8.L2(D_BP_4)
S_DDB05_N: J500.E07(HA05_N) U8.V8(D_BN_5)
S_DDB05_P: J500.E06(HA05_P) U8.V9(D_BP_5)
S_DDB06_N: J500.K11(HA06_N) U8.W6(D_BN_6)
S_DDB06_P: J500.K10(HA06_P) U8.W7(D_BP_6)
S_DDB07_N: J500.J10(HA07_N) U8.M1(D_BN_7)
S_DDB07_P: J500.J09(HA07_P) U8.N1(D_BP_7)
S_DDB08_N: J500.F11(HA08_N) U8.R4(D_BN_8)
S_DDB08_P: J500.F10(HA08_P) U8.P4(D_BP_8)
S_DDB09_N: J500.E10(HA09_N) U8.W1(D_BN_9)
S_DDB09_P: J500.E09(HA09_P) U8.V1(D_BP_9)
S_DDB10_N: J500.K14(HA10_N) U8.U4(D_BN_10)
S_DDB10_P: J500.K13(HA10_P) U8.T4(D_BP_10)
S_DDB11_N: J500.J13(HA11_N) U8.V2(D_BN_11)
S_DDB11_P: J500.J12(HA11_P) U8.V3(D_BP_11)
S_DDB12_N: J500.F14(HA12_N) U8.Z5(D_BN_12)
S_DDB12_P: J500.F13(HA12_P) U8.Z6(D_BP_12)
S_DDB13_N: J500.E13(HA13_N) U8.N3(D_BN_13)
S_DDB13_P: J500.E12(HA13_P) U8.N2(D_BP_13)
S_DDB14_N: J500.J16(HA14_N) U8.Z2(D_BN_14)
S_DDB14_P: J500.J15(HA14_P) U8.Z3(D_BP_14)
S_DDB15_N: J500.F17(HA15_N) U8.L4(D_BN_15)
S_DDB15_P: J500.F16(HA15_P) U8.L3(D_BP_15)
S_SCTRLA_N: J500.G19(LA16_N) U8.G1(SCTRL_AN)
S_SCTRLA_P: J500.G18(LA16_P) U8.F1(SCTRL_AP)
S_SCTRLB_N: J500.E16(HA16_N) U8.V5(SCTRL_BN)
S_SCTRLB_P: J500.E15(HA16_P) U8.V4(SCTRL_BP)
SCL: J4.1 R32.1 U9.8(SCL)
SCP_CLK: J500.B32(DP7_C2M_P) U11.6(A4)
SCP_CSZ: R47.2 U8.C10(SCPENZ) U12.15(1OEZ)
SCP_DI: J500.B36(DP6_C2M_P) R50.2
SCP_DMD_CSZ: J500.C06(DP0_M2C_P) R3.1 U11.8(A6)
SCP_DO: J500.C02(DP0_C2M_P) U11.7(A5)
SDA: J4.2 R31.1 U9.7(SDA)
SEL_0: R42.2 U8.V14(SEL0)
SEL_1: R43.2 U8.Z8(SEL1)
STRB: R35.2 U8.Z9(STROBE)
SW0_1: C13.2 D3.1(ANODE) L5.2 U7.5(SW0) U7.6(SW1)
VADJ: J500.E39(VADJ) J500.F40(VADJ) J500.G39(VADJ) J500.H40(VADJ)
VBIAS: C26.2 C27.1 C98.1 C99.1 C100.1 C101.1 C102.1 C103.1 R6.1 R21.2 R25.1 TP7.1 U7.13(OUT3) U8.C15(VBIAS) U8.C16(VBIAS) U8.V11(VBIAS) U8.V12(VBIAS)
VIO_B_M2C: J500.J39(VIO_B_M2C) J500.K40(VIO_B_M2C)
VOFF: C15.1 C16.1 C17.1 D3.2(CATHODE) Q1.4(S) Q1.SPad(S_pad) R13.1 R14.1 R16.2 U7.9(SUP_OUT1)
VOFFSET: C91.1 C92.1 C93.1 C94.1 C95.1 C96.1 C97.1 D2.1(CATHODE) Q1.1(D) Q1.2(D) Q1.5(D) Q1.6(D) Q1.DPad(D_pad) R5.1 R13.2 TP4.1 U8.A30(VOFFSET) U8.B2(VOFFSET) U8.M30(VOFFSET) U8.Z1(VOFFSET) U8.Z30(VOFFSET)
VREF_A_M2C: J500.H01(VREF_A_M2C)
VREF_B_M2C: J500.K01(VREF_B_M2C)
VRESET: C22.1 C23.2 C24.1 C39.1 C40.1 C41.1 C42.1 C43.1 C44.1 D5.1(A1) R7.1 R23.2 TP6.1 U2.2(S) U8.G4(VRESET) U8.H4(VRESET) U8.J1(VRESET) U8.K1(VRESET)
N15843998: C30.2 R34.2 U8.B18(TEMP_N)
N15845219: R37.1 U10.19(B3)
N15845223: R39.1 U10.17(B5)
N15869127: R48.1 U11.15(B7)
N25259737: C14.2 R18.1
N25259806: C20.1 D4.1(A1) D5.2(K2)
N25259992: C21.1 Q3.3(DRAIN)
N25632003: Q3.1(GATE) R21.1 R24.1
N25668037: R35.1 U10.21(B1)
N25668039: R36.1 U10.20(B2)
N25668080: R38.1 U10.18(B4)
N25668084: R40.1 U10.16(B6)
N25668435: R42.1 U11.21(B1)
N25668437: R43.1 U11.20(B2)
N25668439: R44.1 U11.19(B3)
N25668441: R45.1 U11.18(B4)
N25668443: R46.1 U11.17(B5)
N25668445: R47.1 U11.16(B6)
N25679971: R50.1 U12.13(1B1)
N25707269: Q1.3(G) R16.1 R17.1
N25707305: Q2.3(COLLECTOR) R17.2
N25707317: Q2.2(BASE) R20.2
N25709651: R8.2 U3.3(D) U4.1(G) U5.1(G) U6.2(S)
N25709778: D1.2(ANODE) U5.3(D)
N25709780: D1.1(CATHODE) R9.2
N25709784: R5.2 R9.1
N25709786: R6.2 R10.1
N25709788: R10.2 U4.3(D)
N25709790: R7.2 U2.1(G) U6.3(D)
N25709817: R11.2 R12.1
N25709819: R11.1 U2.3(D)
N25711925: TP26.1 U8.W11(BIST_A)
N25711930: TP25.1 U8.B11(BIST_B)
N25711935: TP24.1 U8.Z20(BIST_C)
N25711940: TP23.1 U8.C18(BIST_D)
N25715846: C30.1 R33.2 U8.B17(TEMP_P)
N25715868: R33.1 U9.2(D+)
N25715880: R34.1 U9.3(D-)
N25721950: R41.2 U10.10(A8)
N25722220: R49.2 U11.10(A8)
N25722470: R52.2 U12.5(1A2)
N25784260: R51.1 U12.10(2B2)

Not connected (* = marked no-connect by the designer): J500 B12(DP7_M2C_P)* B16(DP6_M2C_P)* B17(DP6_M2C_N)* B20(GBTCLK1_M2C_P)* B21(GBTCLK1_M2C_N)* B24(DP9_C2M_P)* B25(DP9_C2M_N)* B28(DP8_C2M_P)* B29(DP8_C2M_N)* C30(SCL)* C31(SDA)* C34(GA0)* D01(PG_C2M)* D04(GBTCLK0_M2C_P)* D05(GBTCLK0_M2C_N)* D29(TCK)* D30(TDI)* D31(TDO)* D33(TMS)* D34(TRST_L)* D35(GA1)* E18(HA20_P)* E19(HA20_N)* E33(HB19_P)* E34(HB19_N)* E36(HB21_P)* E37(HB21_N)* F01(PG_M2C)* F19(HA19_P)* F20(HA19_N)* F37(HB20_P)* F38(HB20_N)* H02(PRSNT_M2C_L)* J18(HA18_P)* J19(HA18_N)* J21(HA22_P)* J22(HA22_N)* J36(HB18_P)* J37(HB18_N)* K16(HA17_P_CC)* K17(HA17_N_CC)* K19(HA21_P)* K20(HA21_N)* K22(HA23_P)* K23(HA23_N)* K37(HB17_P_CC)* K38(HB17_N_CC)*; U1 5(ERROR)*; U7 2(FB4)* 3(BASE)*; U8 A18(PROG_FUSE_EN)* C8(TEST_MUX)* D12(MBRST_0)* D13(MBRST_1)* D14(MBRST_2)* D15(MBRST_3)* D16(MBRST_4)* D17(MBRST_5)* D18(MBRST_6)* D19(MBRST_7)* U12(MBRST_8)* U13(MBRST_9)* U14(MBRST_10)* U15(MBRST_11)* U16(NC)* U17(NC)* U18(NC)* U19(NC)* W19(TP_2)* W20(TP_1)* Z19(TP_0)*; U9 4(THERM)* 6(ALERT)*; U10 9(A7)* 14(B8)* 15(B7)*; U11 14(B8)*; U12 12(1B2)*

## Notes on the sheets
sheet 1
- Revision A:
  Initial Release
  Revision B:
  R25 tolerance changed from 0.5% to 0.1%
  R26 tolerance changed from 0.5% to 0.1%
  Revision C:
  Removed J1 & J2 Flex Cable Interface
  Added J500 FMC Connector
- DLP079
sheet 2
- Secondary Controller Bus A
- Main Controller Bus A
- Secondary Controller Bus B
- Main Controller Bus B
- Total Power Transfer:
  1A at 12V
- Note: Do not install R3 if
  there is a pull-up on the
  SCP_DMD_CSZ signal on the
  Main board.
- Note: Only install one 1K Ohm
  pull-up resistor on DAD_OEZ. If
  DAD_OEZ pull-up is installed on
  Main board side, do not install
  R1.
- Note: R4 and C5 are specific
  values selected to delay ASIC
  driven DAD_OEZ to allow the DMD
  enough time to park properly.
  Recommend installing values as
  shown.
- DLP079
sheet 3
- NOTES, UNLESS OTHERWISE SPECIFIED:
- 1. The netname "DMD_P3P3V" represents connection to the +3.3V digital power plane.
- 2. The symbol
- represents connection to the digital ground plane.
- 3. A "Z" suffix on a signal name indicates an active low signal.
- 4. All components with designators "U", "D", "Y" and "Q" are electrostatic discharge sensitive.
- 5. All resistor values are in ohms, 1/16W and 5% unless otherwise specified.
sheet 4
- U8
  DLP470NE
- J500
  HPC FMC CONNECTOR
- A/B DMD DATA (DD_AP[15:0], DD_AN[15:0], DD_BP[15:0], DD_BN[15:0])
- From
  Secondary
  Controller
- A/B DMD CLK (DCLK_AP, DCLK_AN, DCLK_BP, DCLK_BN)
- A/B SCTRL (SCTRL_AN, SCTRL_AP, SCTRL_BN, SCTRL_BP)
- C/D DMD DATA (DD_CP[15:0], DD_CN[15:0], DD_DP[15:0], DD_DN[15:0])
- C/D DMD CLK (DCLK_CP, DCLK_CN, DCLK_DP, DCLK_DN)
- From
  Primary
  Controller
- C/D SCTRL (SCTRL_CN, SCTRL_CP, SCTRL_DN, SCTRL_DP)
- U10, U11, U12
  Level Translators
  3.3V->1.8V
- DAD CONTROL (STROBE, MODE[0], SEL[1:0], ADDR[3:0], OEZ)
- SCP CONTROL  (CLK, DO, DI, ENZ, IRQZ)
- DMD_RSTZ
- U1
  VREG
  3.3V->1.8V
- U7
  DMD Power Supplies
- 3.3V
- VOFFSET
- VBIAS
- VRESET
- PG_OFFSET
- EN_OFFSET
- PAGE 3
- PAGE 4
- PAGE 5 & 6
- DLP079
sheet 5
- Power Down Circuitry
- Do Not Install.
  Used to Adjust
  Vreset Rise Time
- 10.0V
- 11V protection diode
- -14.0V
- 18.0V
- DMD Power Supplies
- DLP079
sheet 6
- DLP079
- DLP079
sheet 7
- S410 DMD Mounting Instances
- DMD Power/Gnd
- DLP079
sheet 8
- DMD Data/Control
- DLP079
